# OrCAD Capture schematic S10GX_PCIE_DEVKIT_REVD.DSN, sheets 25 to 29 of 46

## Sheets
25 FMC Port A: size C
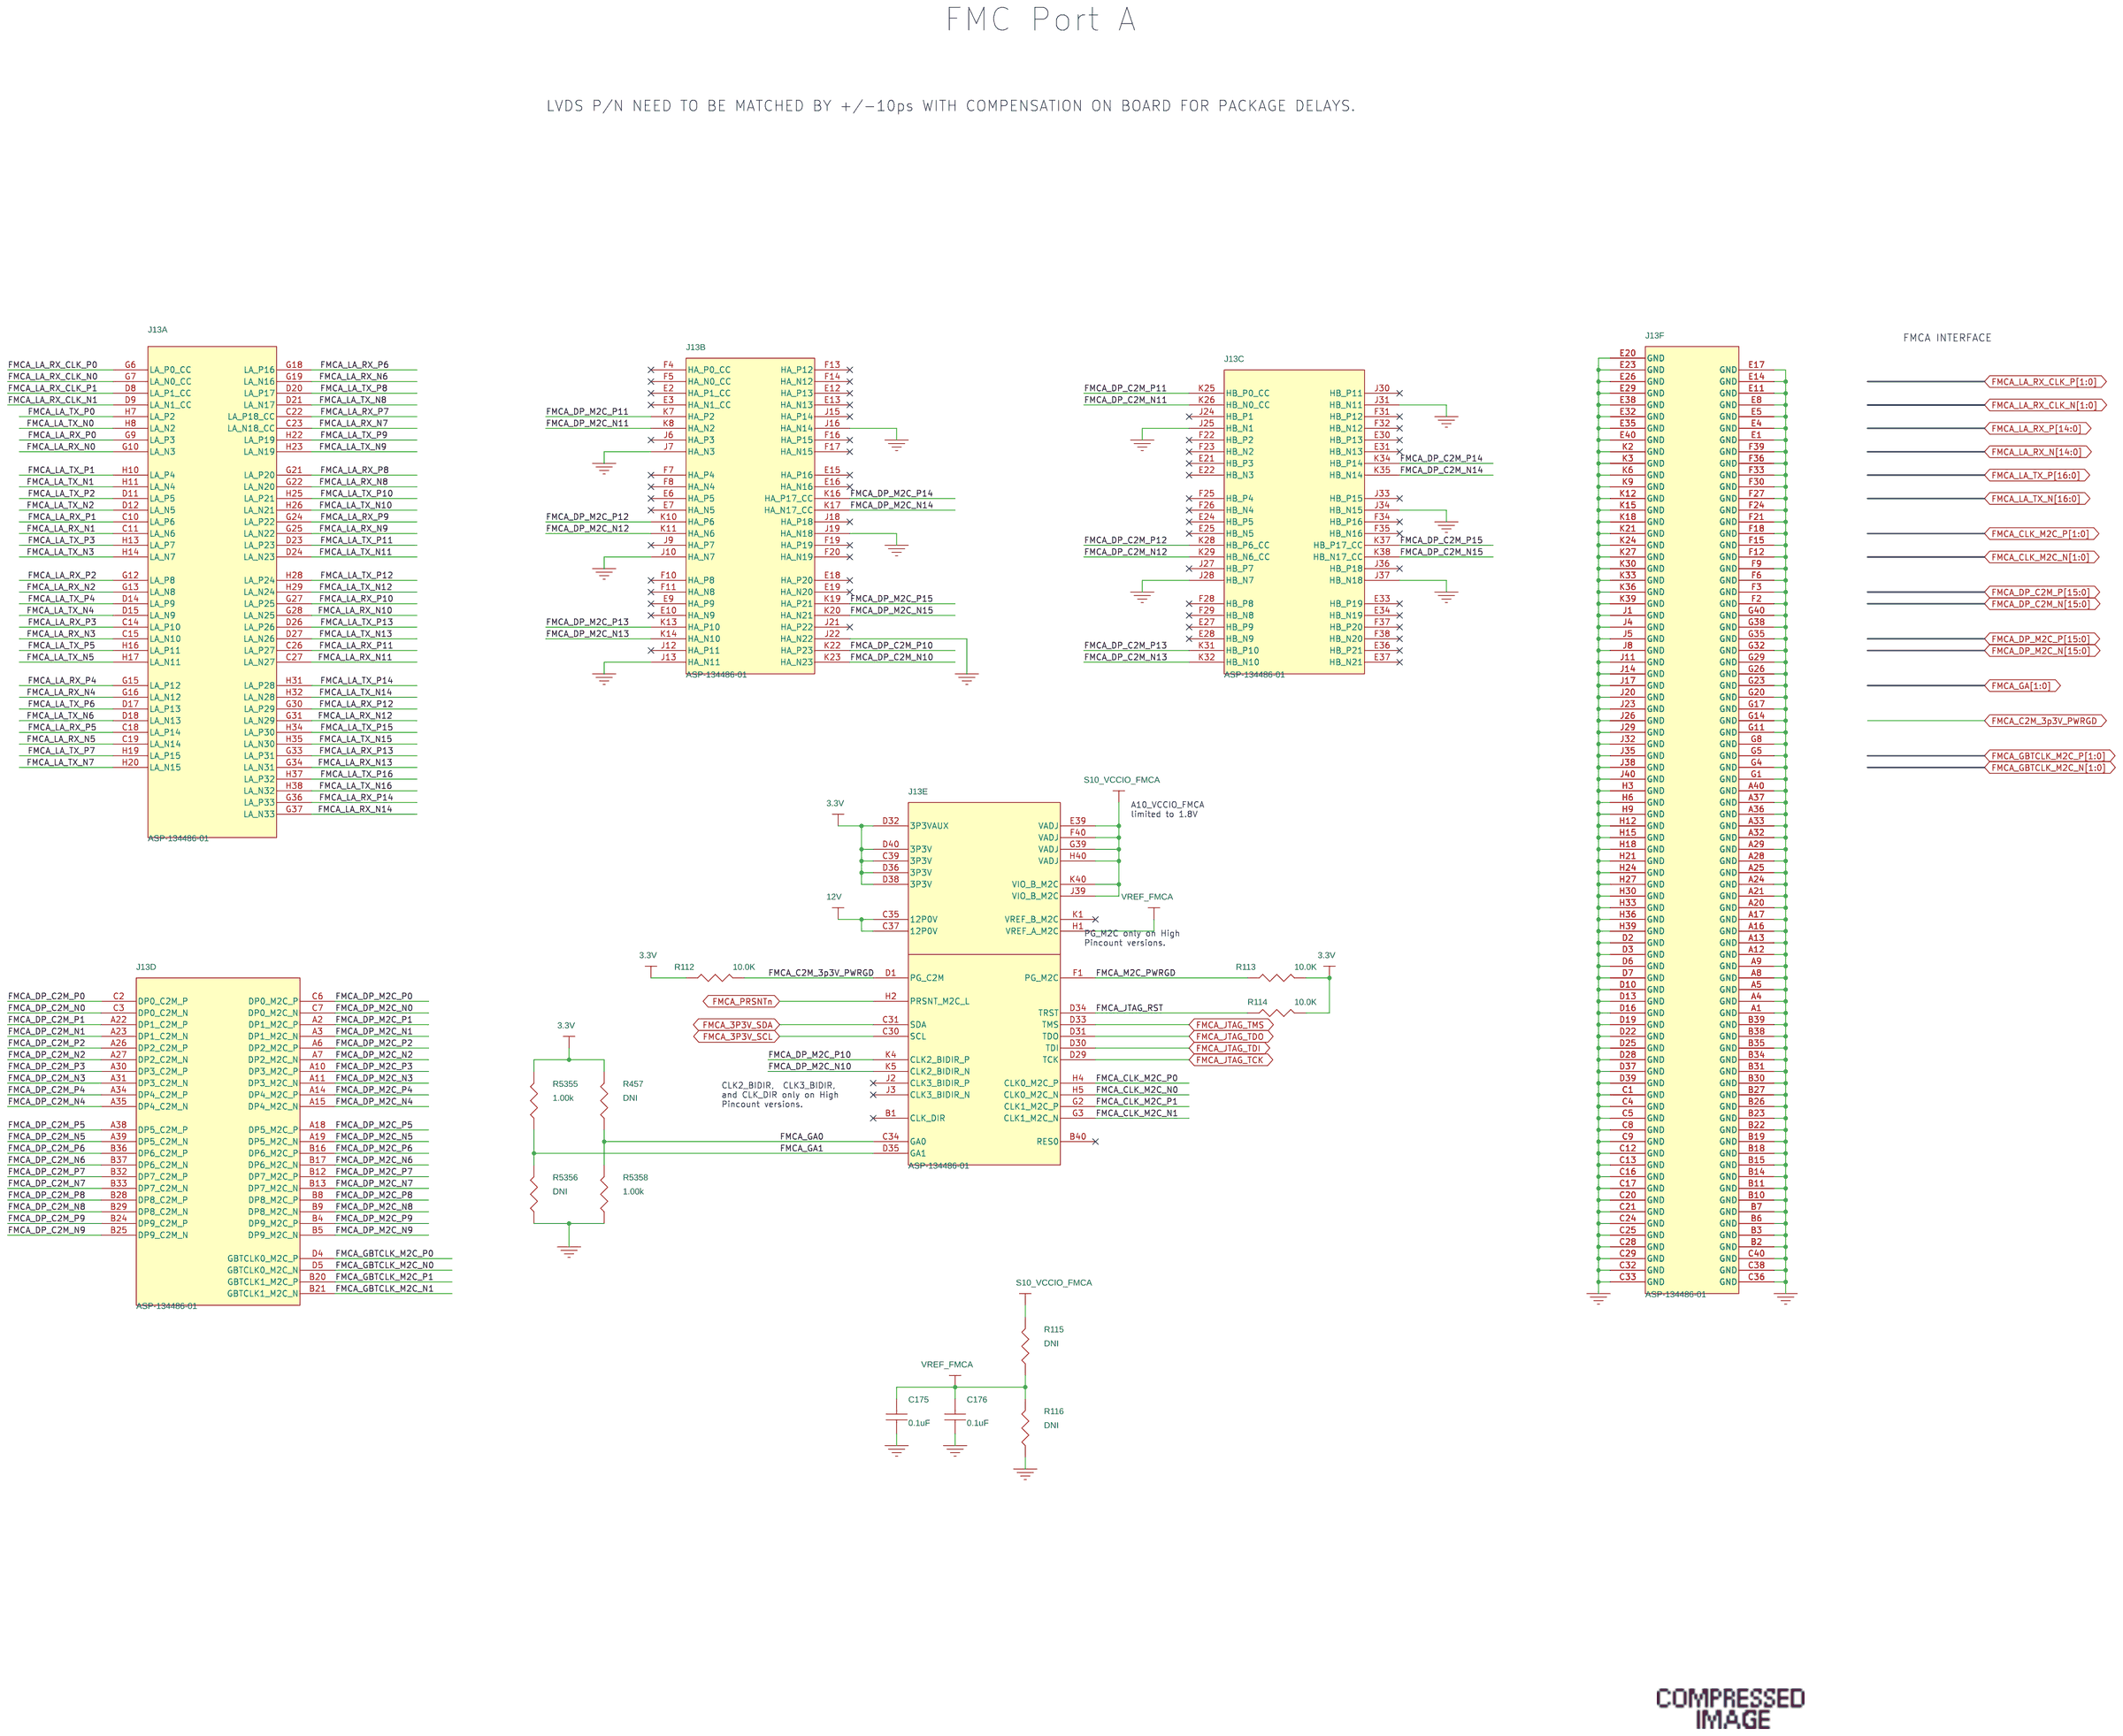
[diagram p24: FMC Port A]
26 Blank
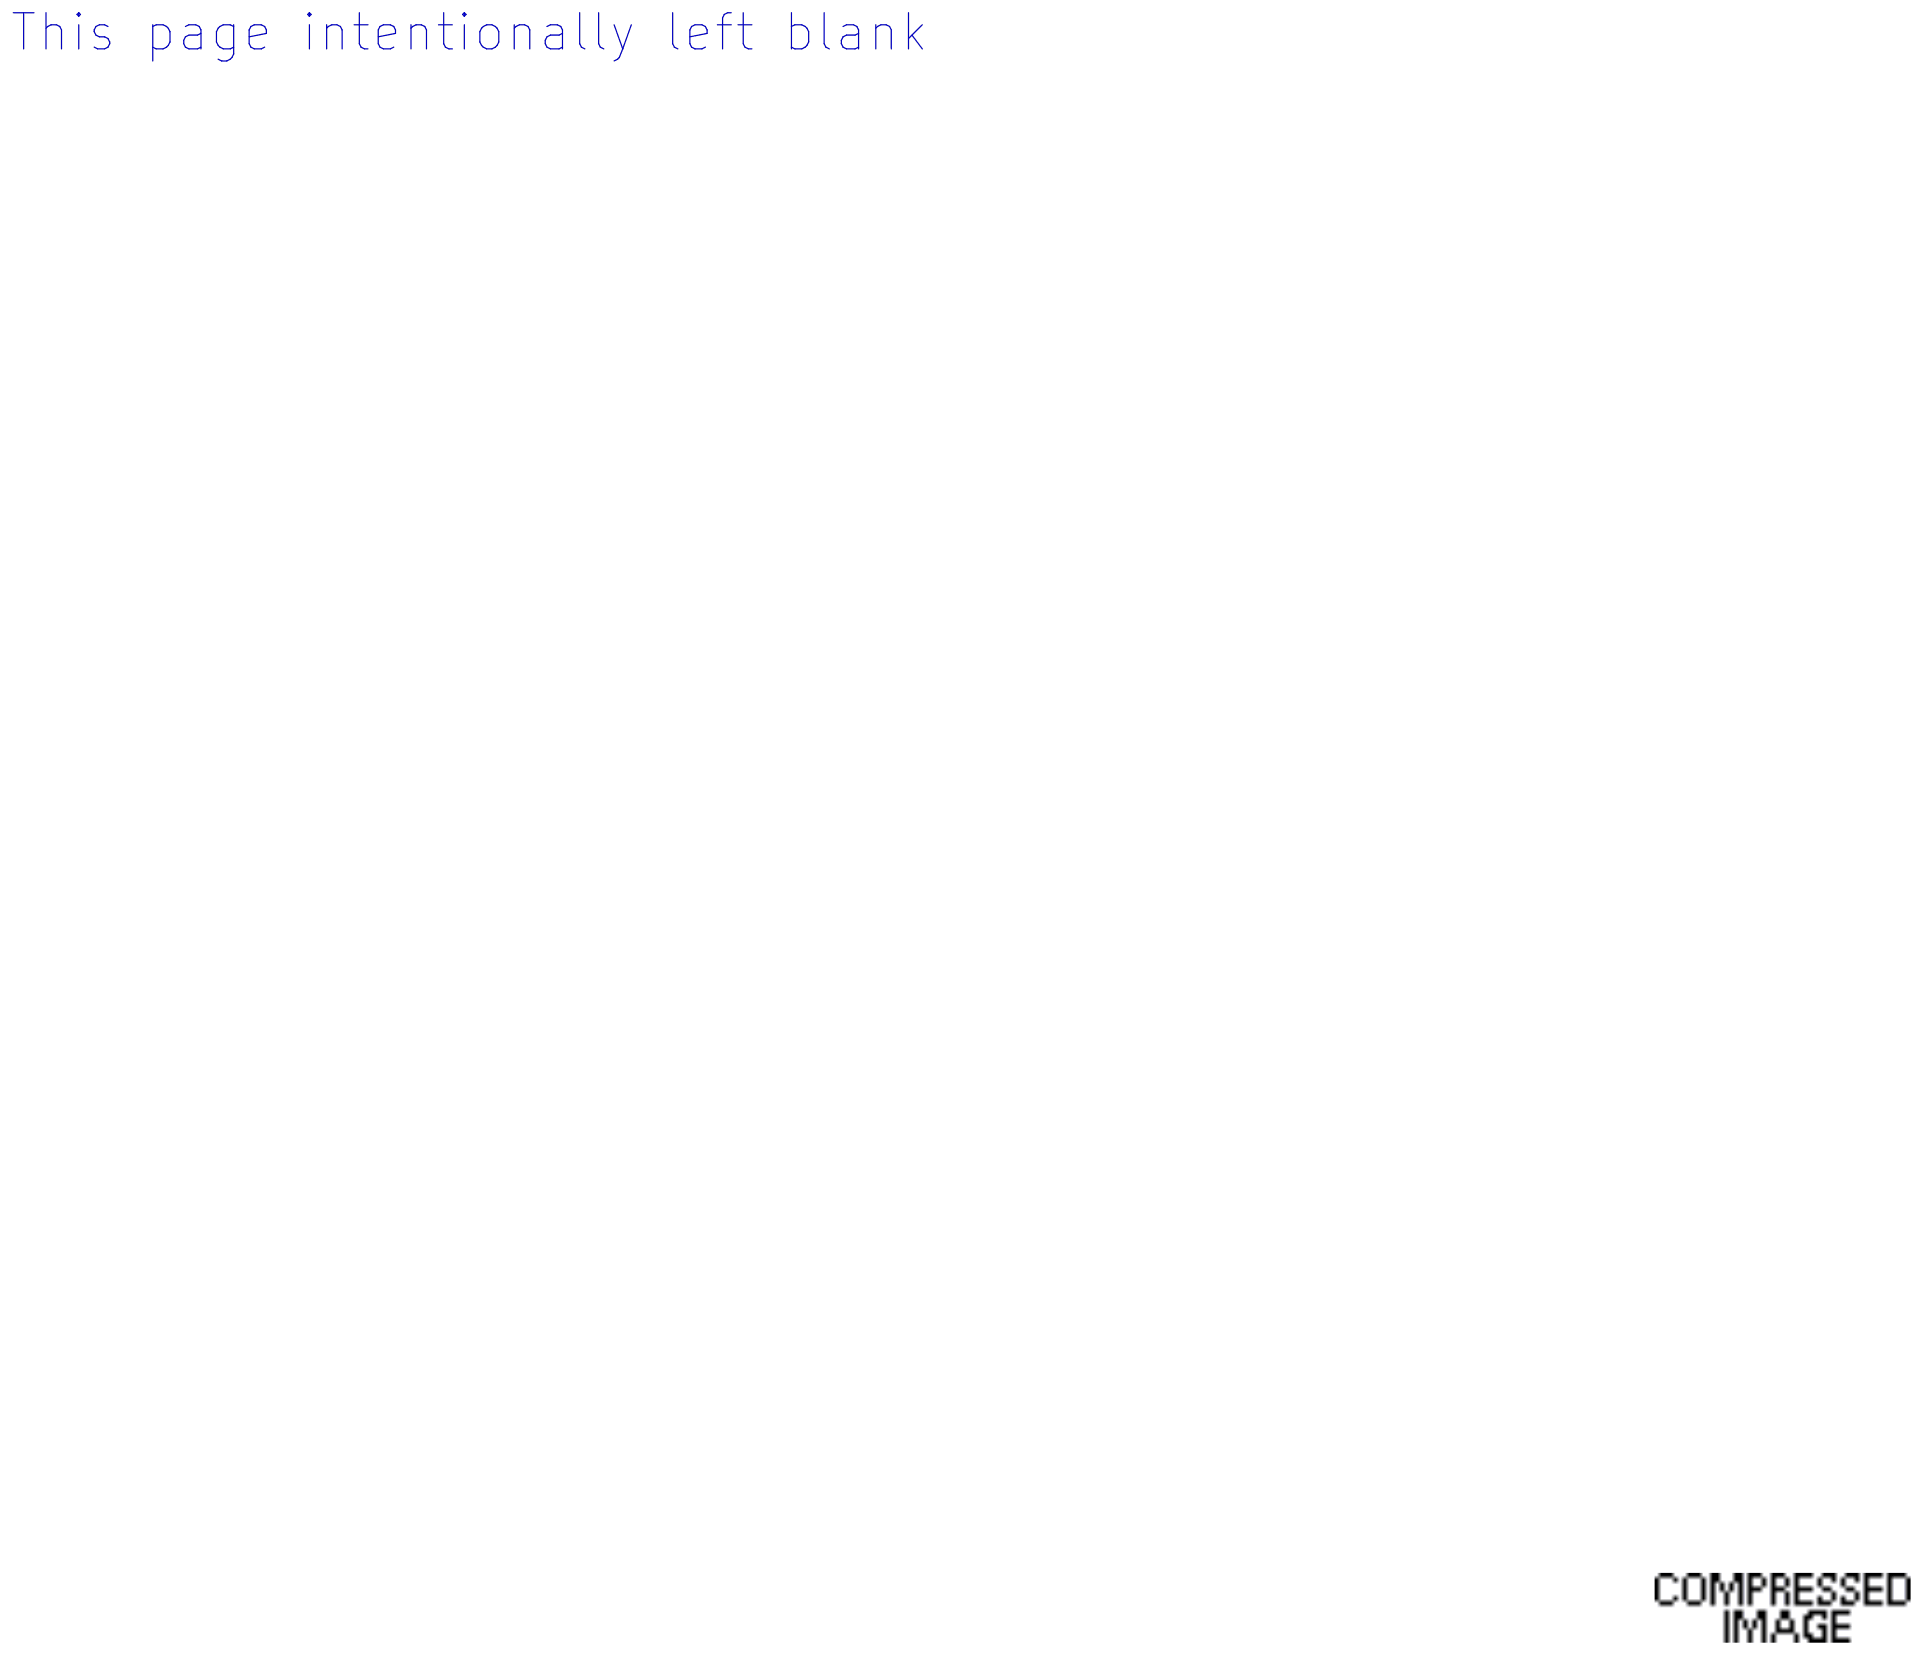
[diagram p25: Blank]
27 QSFP: size C
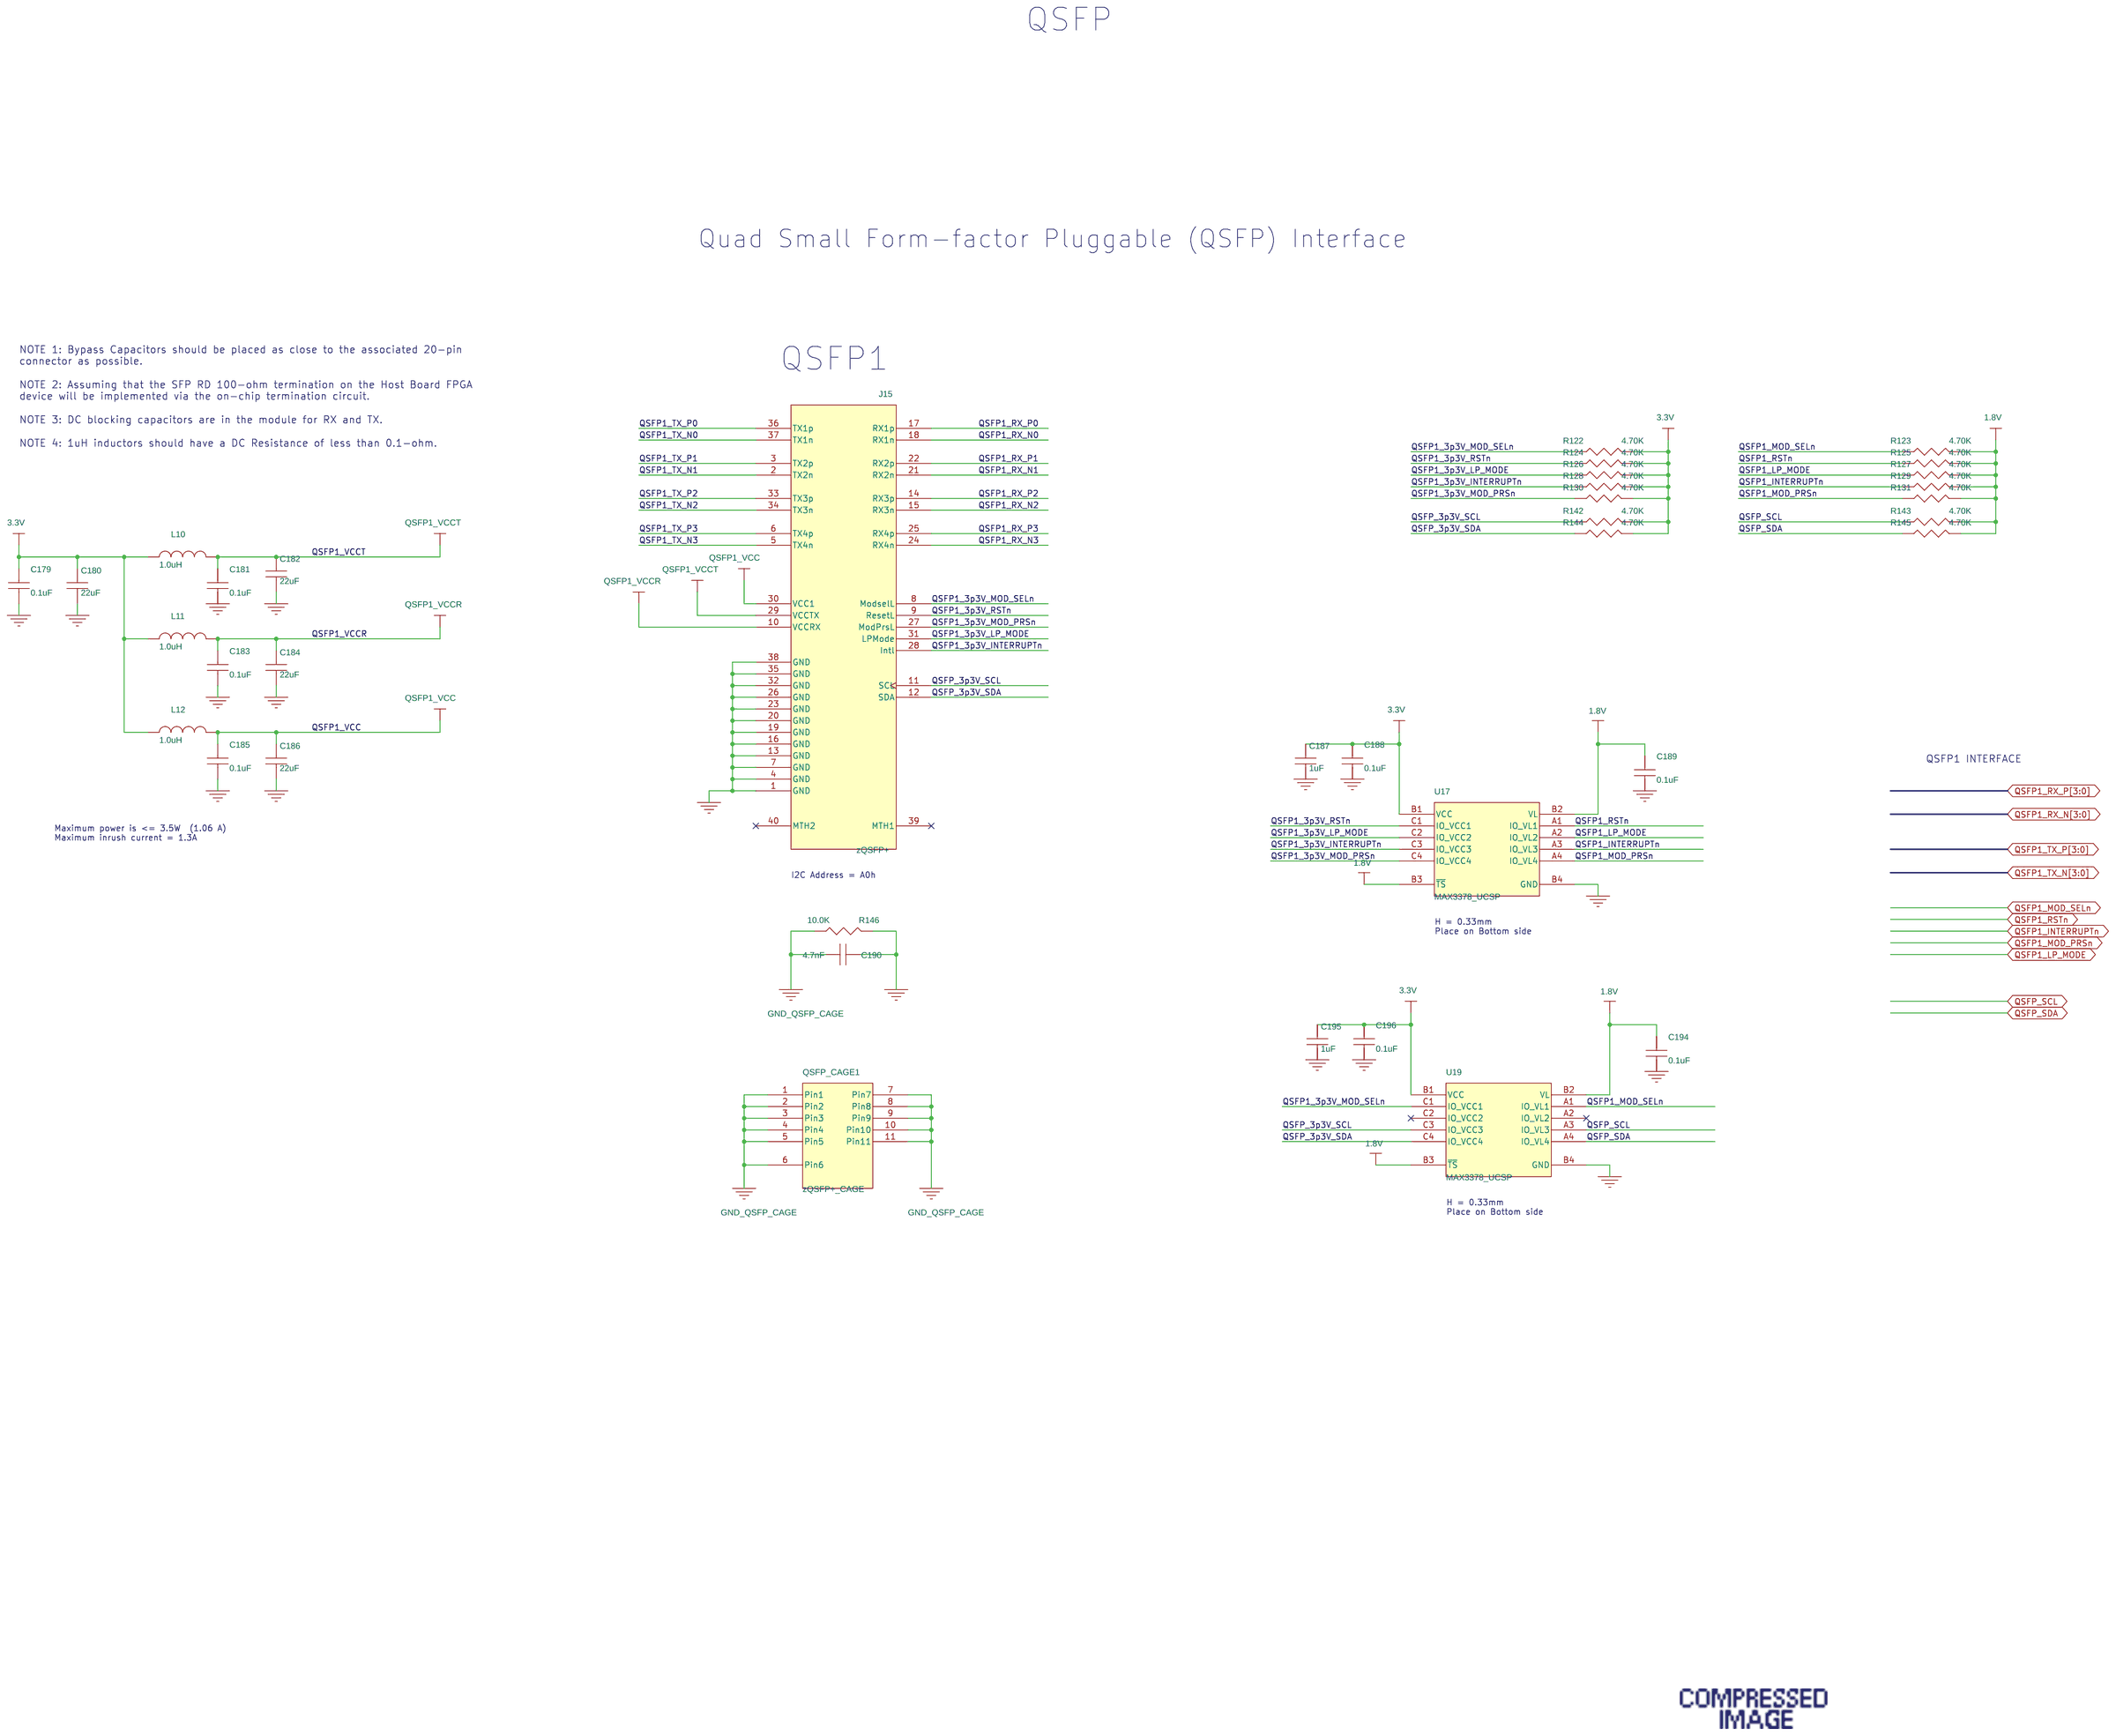
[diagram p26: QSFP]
28 12G SDI: size C
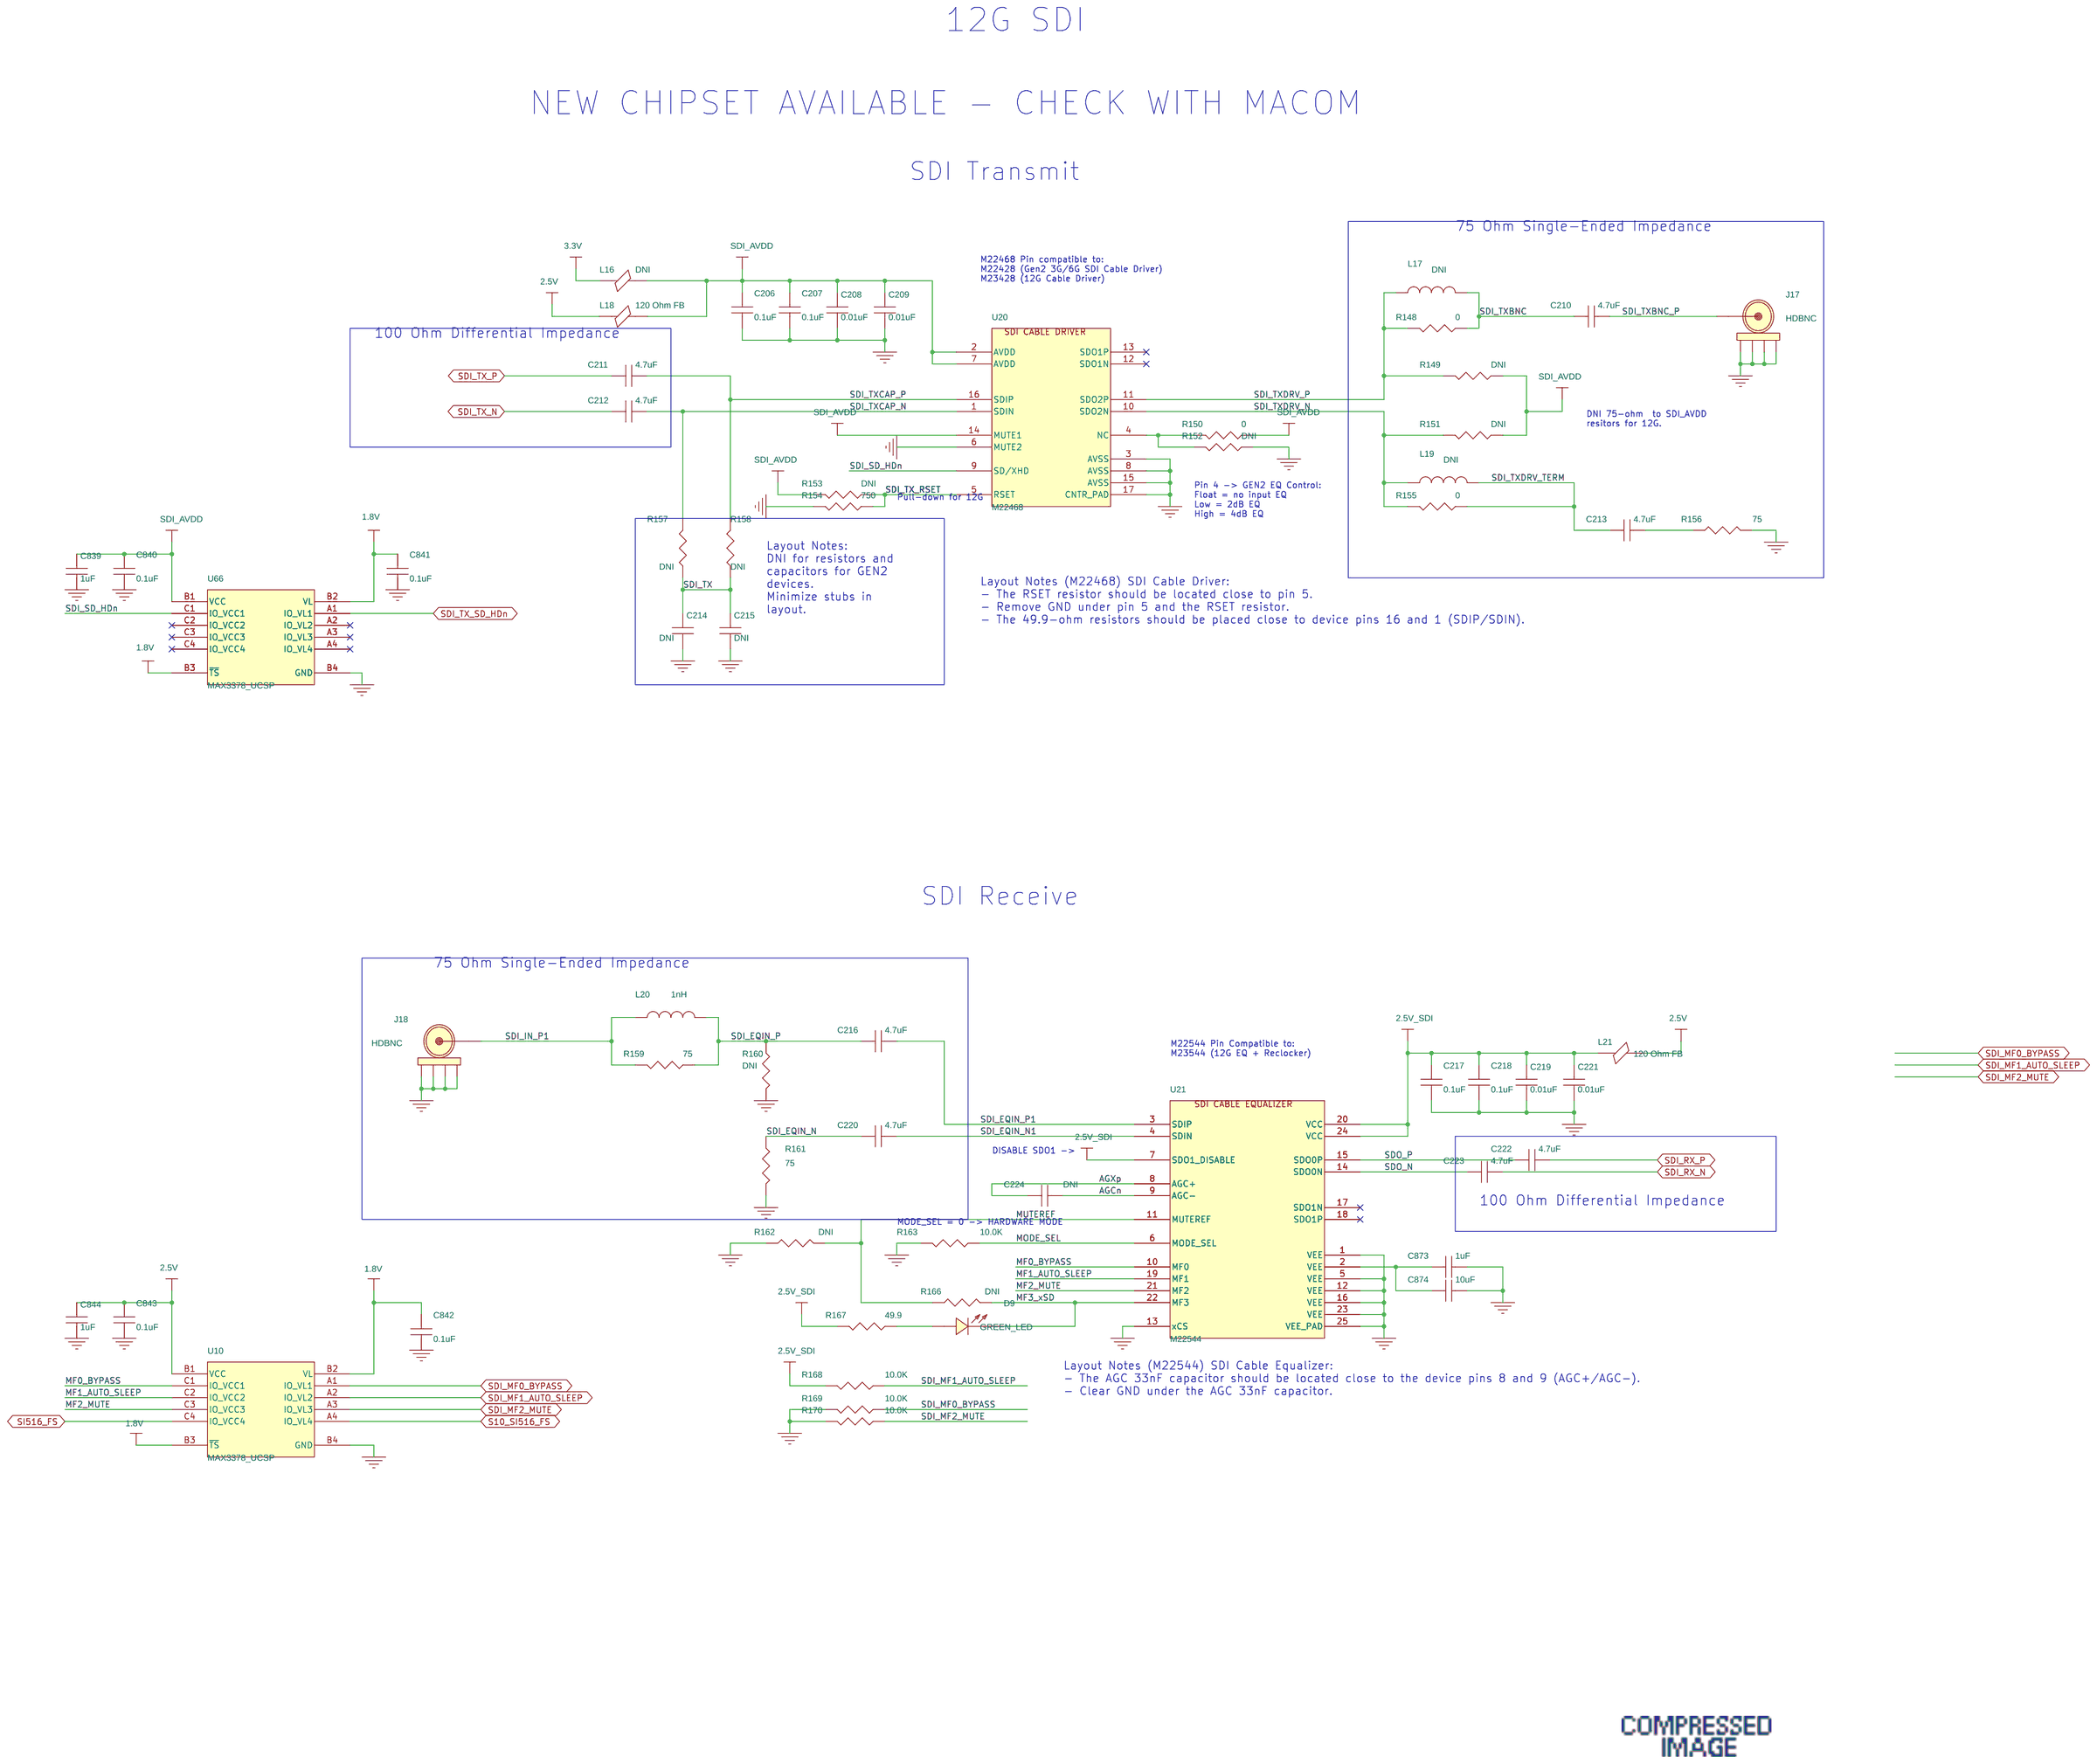
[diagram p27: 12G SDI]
29 User PB, SW, I/Os: size C
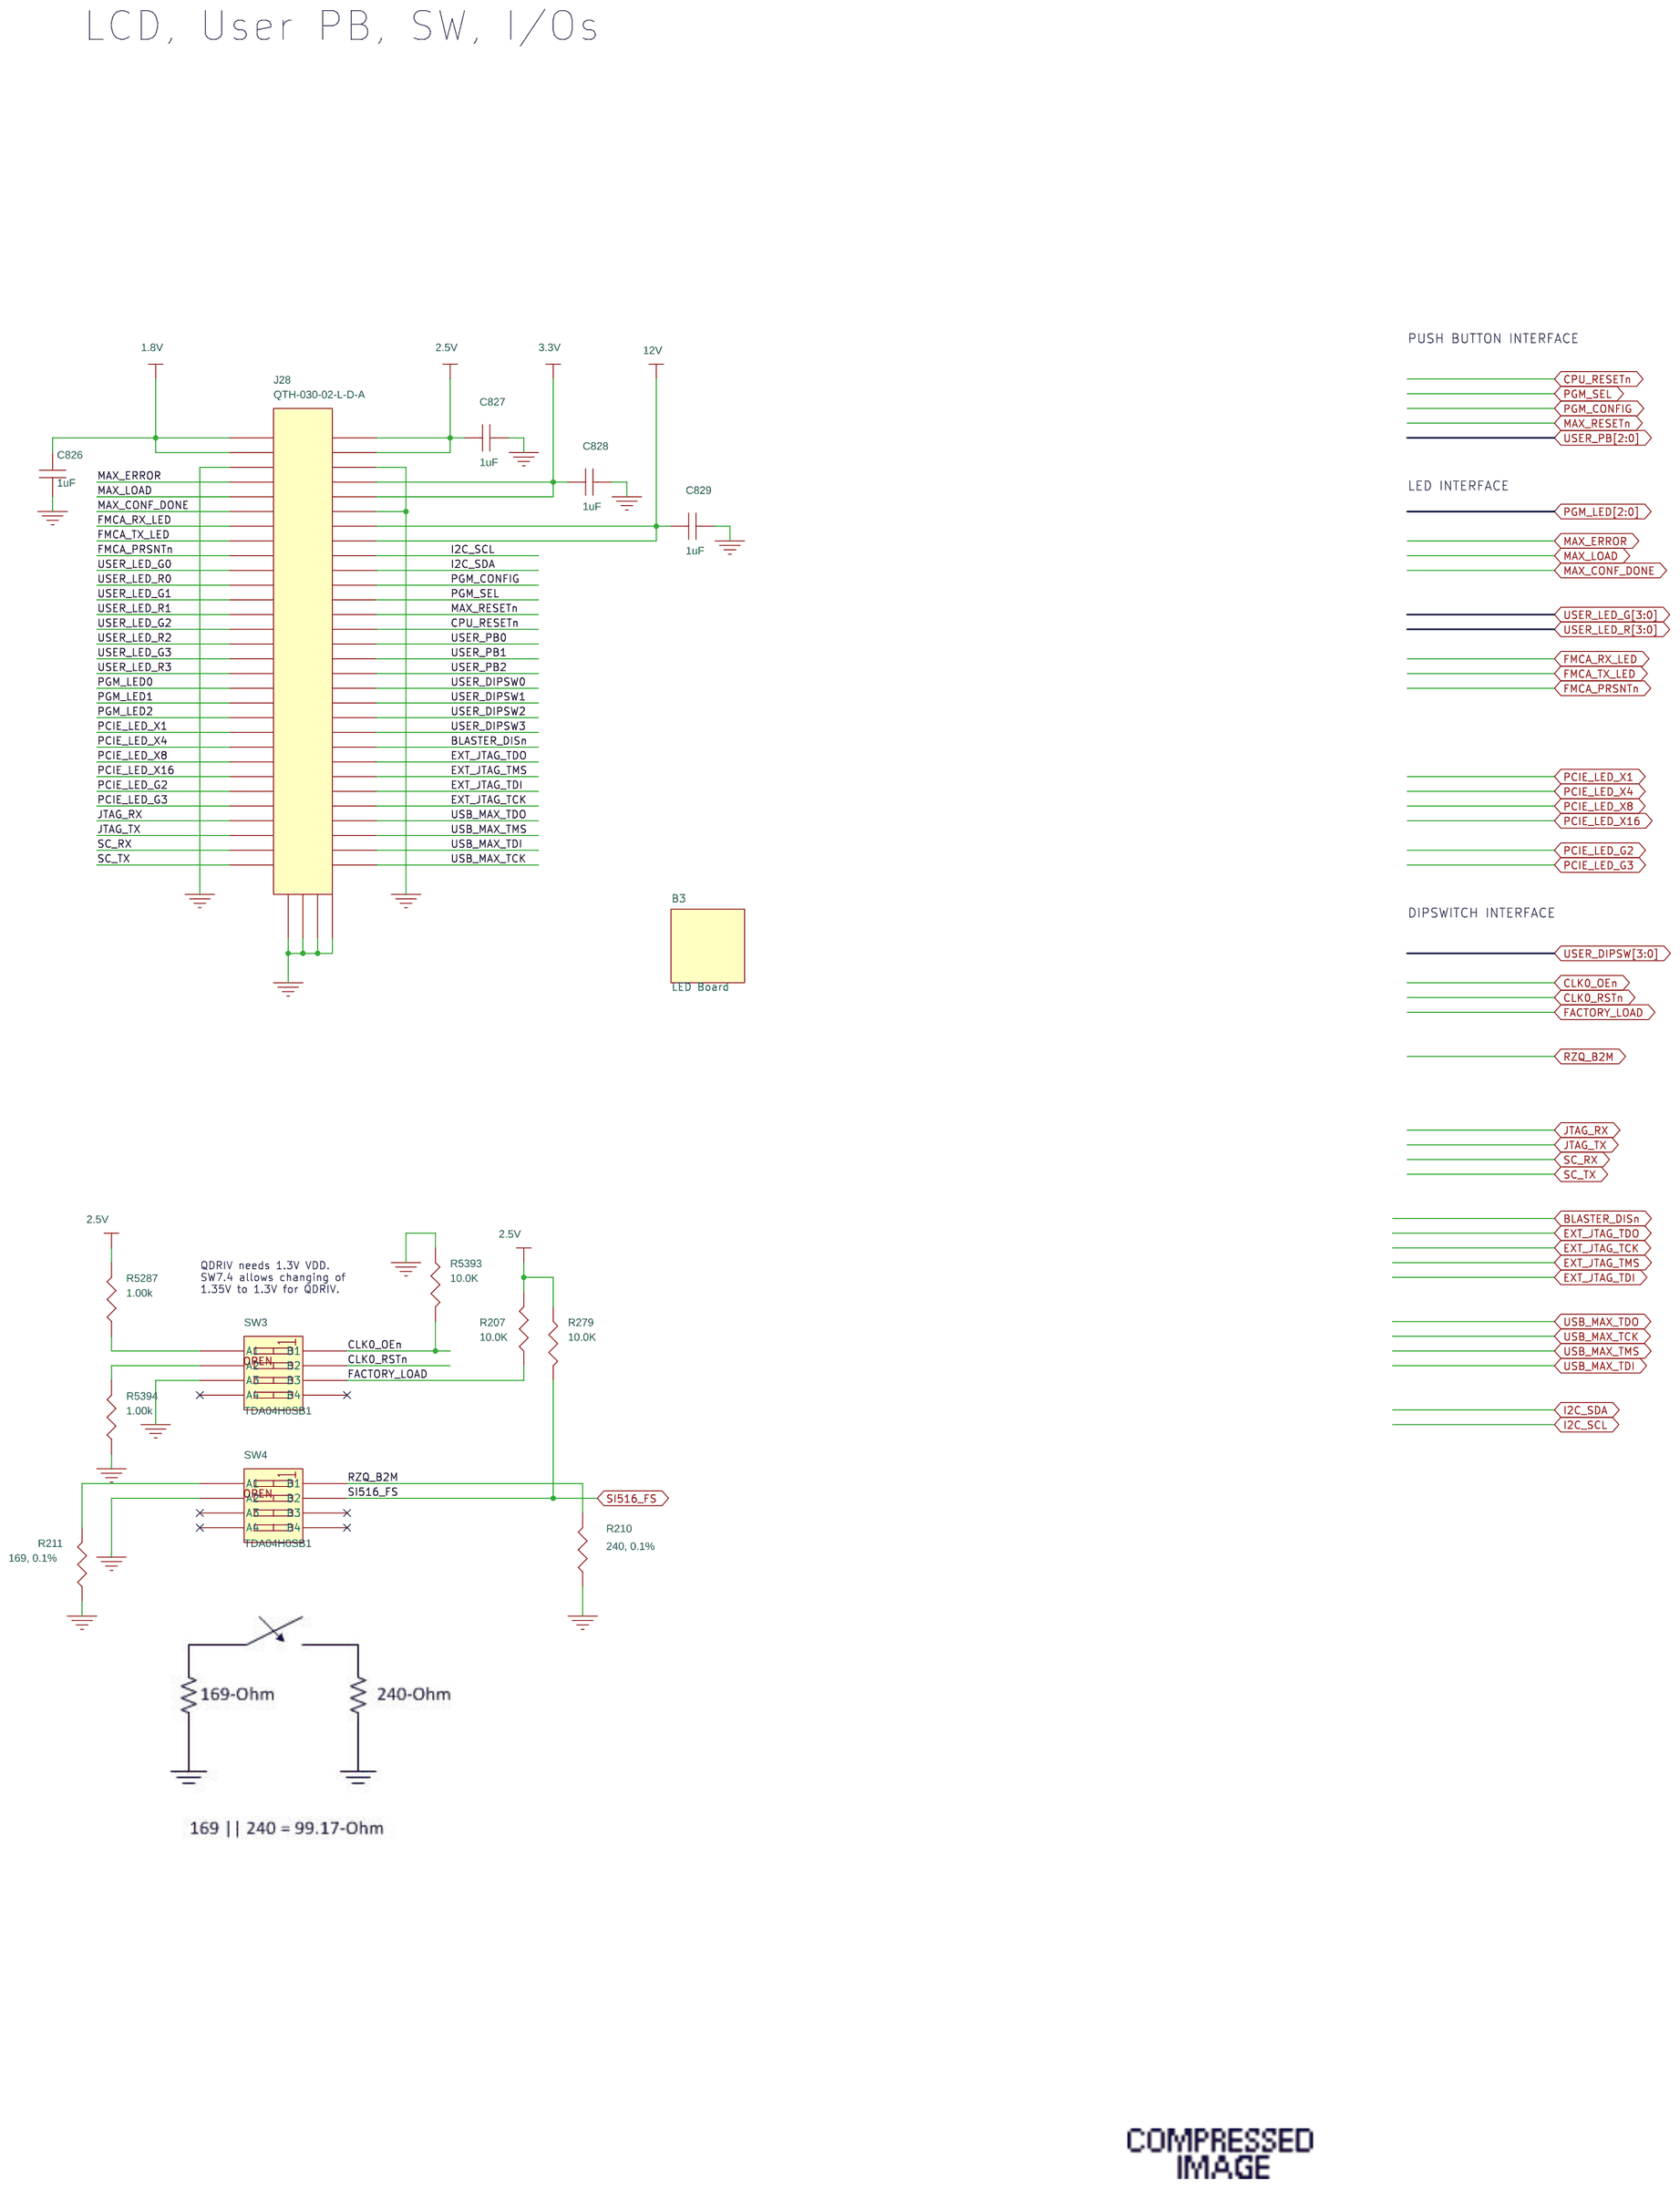
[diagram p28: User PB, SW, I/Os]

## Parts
sheet 12G SDI
C206  0.1uF  [0402]
C207  0.1uF  [0402]
C208  0.01uF  [0402]
C209  0.01uF  [0402]
C210  4.7uF  [0402]
C211  4.7uF  [0402]
C212  4.7uF  [0402]
C213  4.7uF  [0402]
C214  DNI  [0402]
C215  DNI  [0402]
C216  4.7uF  [0402]
C217  0.1uF  [0402]
C218  0.1uF  [0402]
C219  0.01uF  [0402]
C220  4.7uF  [0402]
C221  0.01uF  [0402]
C222  4.7uF  [0402]
C223  4.7uF  [0402]
C224  DNI  [0402]
C839  1uF  [0402]
C840  0.1uF  [0402]
C841  0.1uF  [0402]
C842  0.1uF  [0402]
C843  0.1uF  [0402]
C844  1uF  [0402]
C873  1uF  [0402]
C874  10uF  [0402]
D9  GREEN_LED  [LED_0603]
J17  HDBNC  [HDBNC_RA_JACK_RECEP]
J18  HDBNC  [HDBNC_RA_JACK_RECEP]
L16  DNI  [0603]
L17  DNI  [0402]
L18  120 Ohm FB  [0603]
L19  DNI  [0402]
L20  1nH  [0402]
L21  120 Ohm FB  [0603]
R148  0  [0402]
R149  DNI  [0402]
R150  0  [0402]
R151  DNI  [0402]
R152  DNI  [0402]
R153  DNI  [0603]
R154  750  [0603]
R155  0  [0402]
R156  75  [0402]
R157  DNI  [0402]
R158  DNI  [0402]
R159  75  [0402]
R160  DNI  [0402]
R161  75  [0402]
R162  DNI  [0402]
R163  10.0K  [0402]
R166  DNI  [0402]
R167  49.9  [0402]
R168  10.0K  [0402]
R169  10.0K  [0402]
R170  10.0K  [0402]
U10  MAX3378_UCSP  [UCSP-12]
U20  M22468  [MLF-16]
U21  M22544  [QFN24]
U66  MAX3378_UCSP  [UCSP-12]
sheet FMC Port A
C175  0.1uF  [0402]
C176  0.1uF  [0402]
J13  ASP-134486-01  [10x40_ASP_Vita57]  (sections A,B,C,D,E,F)
R112  10.0K  [0402]
R113  10.0K  [0402]
R114  10.0K  [0402]
R115  DNI  [0402]
R116  DNI  [0402]
R457  DNI  [0402]
R5355  1.00k  [0402]
R5356  DNI  [0402]
R5358  1.00k  [0402]
sheet QSFP
C179  0.1uF  [0402]
C180  22uF  [1210]
C181  0.1uF  [0402]
C182  22uF  [1210]
C183  0.1uF  [0402]
C184  22uF  [1210]
C185  0.1uF  [0402]
C186  22uF  [1210]
C187  1uF  [0402]
C188  0.1uF  [0402]
C189  0.1uF  [0402]
C190  4.7nF  [0402]
C194  0.1uF  [0402]
C195  1uF  [0402]
C196  0.1uF  [0402]
J15  zQSFP+  [170432-0001]
L10  1.0uH  [IND_WURTH_74479775210]
L11  1.0uH  [IND_WURTH_74479775210]
L12  1.0uH  [IND_WURTH_74479775210]
QSFP_CAGE1  zQSFP+_CAGE  [QSFP_CAGE1]
R122  4.70K  [0402]
R123  4.70K  [0402]
R124  4.70K  [0402]
R125  4.70K  [0402]
R126  4.70K  [0402]
R127  4.70K  [0402]
R128  4.70K  [0402]
R129  4.70K  [0402]
R130  4.70K  [0402]
R131  4.70K  [0402]
R142  4.70K  [0402]
R143  4.70K  [0402]
R144  4.70K  [0402]
R145  4.70K  [0402]
R146  10.0K  [0402]
U17  MAX3378_UCSP  [UCSP-12]
U19  MAX3378_UCSP  [UCSP-12]
sheet User PB, SW, I/Os
B3  LED Board
C826  1uF  [0402]
C827  1uF  [0402]
C828  1uF  [0402]
C829  1uF  [0402]
J28  QTH-030-02-L-D-A  [QTH-030]
R207  10.0K  [0402]
R210  240, 0.1%  [0603]
R211  169, 0.1%  [0603]
R279  10.0K  [0402]
R5287  1.00k  [0402]
R5393  10.0K  [0402]
R5394  1.00k  [0402]
SW3  TDA04H0SB1  [DIPSWITCH_SMT_QUAD]
SW4  TDA04H0SB1  [DIPSWITCH_SMT_QUAD]

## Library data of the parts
C188 C189 C194 C196 C206 C207 C217 C218 C840-C843 = CAP: CAP - CERAMIC,  0.1UF 0402 25VDC Y5V; Dielectric: Y5V; Item Num: P03-15057R; LIFECYCLE_PHASE: Active; Lead Free Status: Lead Free; MFR_LIFECYCLE: Active; Manufacturer: Murata; Manufacturer Part Num: GRM155F51E104ZA01D; Num Pins: 2; PART_SUBCLASS: CAPACITORS; Part Class: CAPACITORS; RATED_VOLTAGE: 25V; RoHS Compliant: RoHS Compliant; Tolerance: +80%/-20%
C208 C209 C214 C215 C219 C221 = CAP: CAP - CER, 10NF, 50V, +/-10%, X7R, 0402 SMD; Dielectric: X5R; Item Num: P03-16318R; Lead Free Status: Yes; Manufacturer: Murata; Manufacturer Part Num: GRM155R71H103KA88D; Manufacturer's Part No.: GRM155R71H103KA88D; Num Pins: 2; Part Class: CAPACITORS; Price: 0.07; RoHS Compliant: Yes; Tolerance: 10%
C210-C213 C216 C220 C222 C223 = CAP: CAP - CERAMIC, 4.7UF, 6.3V, 10%, X5R, 0402; AGILE_LINK: http://sj-agile9app/Agile/PLMServlet?action=OpenEmailObject&classid=10000&objid=257560276; Item Num: P03-17432R; LIFECYCLE_PHASE: Active; Lead Free Status: Not Lead Free; MFR_LIFECYCLE: Active; Manufacturer: Murata; Manufacturer Part Num: GRM155R60J475ME87D; Num Pins: 2; PART_SUBCLASS: CAPACITORS; RATED_VOLTAGE: 6.3V; RoHS Compliant: RoHS Compliant; TOLERANCE: +/-10%
C224 = CAP: CAP, CERAMIC, 33000PF, 0402, 10%, 10VDC, X5R; Item Num: P03-15011R; Lead Free Status: Yes; Manufacturer: Murata; Manufacturer Part Num: GRM155R61A333KA01D; Num Pins: 2; Part Class: CAPACITORS; RoHS Compliant: Yes
C187 C195 C826-C829 C839 C844 C873 = CAP: CAP - CER, 1uF, 10V, +/-10%, X5R, 0402; Item Num: P03-15479R; Lead Free Status: Yes; Manufacturer: Murata; Manufacturer Part Num: GRM155R61A105KE15D; Num Pins: 2; Part Class: CAPACITORS; RoHS Compliant: Yes
C874 = CAP: CAP - 10UF 6.3V CERAMIC CAPACITOR X5R 0402; Item Num: P03-17886R; Lead Free Status: Yes; Manufacturer: Murata; Manufacturer Part Num: GRM155R60J106ME44D; Num Pins: 2; Part Class: CAPACITORS; RoHS Compliant: Yes
D9 = LED_WURTH: LED - BRIGHT GREEN, VF=2V, IF=0.03A, 0603; Item Num: P09-21344R; LIFECYCLE_PHASE: Active; Lead Free Status: Lead Free; Manufacturer: Wurth Electroniks; Manufacturer Part Num: 150060VS75000; Num Pins: 2; PART_SUBCLASS: LEDS; Part Class: LEDS; RoHS Compliant: RoHS Compliant
J17 J18 = CONN,_mini_SMB,_THM,_RA: 75ohm High Density BNC Jacks; Item Num: P23-38673R; Manufacturer: Samtec; Manufacturer Part Num: HDBNC-J-P-GN-RA-BH2
L16 L18 L21 = BEAD_FERRITE_SM: IND - EMIFIL FERRITE BEAD, 120 OHM, 25%, 0603; Item Num: P04-16045R; Lead Free Status: No; Manufacturer: Murata; Manufacturer Part Num: BLM18PG121SN1; Num Pins: 2; Part Class: Inductors; Price: 0; RoHS Compliant: Yes
L17 L19 = INDUCTOR: IND - 3.9NH, 5%, 0402; AGILE_LINK: http://sj-agile9app/Agile/PLMServlet?action=OpenEmailObject&classid=10000&objid=259659196; Item Num: P04-16446R; LIFECYCLE_PHASE: Preliminary; Lead Free Status: Lead Free; MFR_LIFECYCLE: Active; Manufacturer: Coilcraft; Manufacturer Part Num: 0402CS-3N9XJLx; Num Pins: 2; PART_SUBCLASS: INDUCTORS; RoHS Compliant: RoHS Compliant
L20 = INDUCTOR: INDUCTOR FILM RF 1NH AT 500MHZ 400MA 0402 (Murata); AGILE_LINK: http://sj-agile9app/Agile/PLMServlet?action=OpenEmailObject&classid=10000&objid=215176093; Item Num: P04-17107R; LIFECYCLE_PHASE: Active; MFR_LIFECYCLE: Active; Manufacturer: Murata; Manufacturer Part Num: LQP15MN1N0B02D; Num Pins: 2; PACKAGING: Tape Reel; PART_SUBCLASS: INDUCTORS; RoHS Compliant: RoHS Compliant
R148 R150 R155 = RESISTOR: RES ZERO OHM 1/16W 5% 0402 SMD; Altera Part No.: P02-14020R; Item Num: P02-14020R; Lead Free Status: No; Manufacturer: Panasonic; Manufacturer Part Num: ERJ-2GE0R00X; Num Pins: 2; Part Class: RESISTORS; RoHS Compliant: Yes; Tolerance: 5%
R149 R151 R156 R159-R161 = RESISTOR: RES, 75 OHM, 5%, 1/16W, 0402; Item Num: P02-14103R; Lead Free Status: No; Manufacturer: Panasonic; Manufacturer Part Num: ERJ-2GEJ750X; Num Pins: 2; Part Class: Resistors; Price: 0
R152 R162 R166 = RESISTOR: RES ZERO OHM 1/16W 5% 0402 SMD; Altera Part No.: P02-14020R; Item Num: P02-14020R; Lead Free Status: No; Manufacturer: Panasonic; Manufacturer Part Num: ERJ-2GE0R00X; Num Pins: 2; Part Class: RESISTORS; Price: 0; RoHS Compliant: Yes; Tolerance: 5%
R153 R154 = RESISTOR: RES, 750 OHMS, 5%, 1/10W, 0603; Item Num: P02-14118R; Lead Free Status: No; Manufacturer: Panasonic; Manufacturer Part Num: ERJ-3GEYJ751V; Num Pins: 2; Part Class: Resistors; Price: 0
R157 R158 R167 = RESISTOR: RES, 49.9 OHMS, 1%, 1/16W, 0402; Item Num: P02-14101R; Lead Free Status: Yes; Manufacturer: NIC Components Corp.; Manufacturer Part Num: NRC04F49R9TRF; Num Pins: 2; Part Class: Resistors; Price: 0
R112-R114 R146 R163 R168-R170 R207 R279 R5393 = RESISTOR: RES,10.0K OHMS,1.0%,1/16W, 0402; AGILE_LINK: http://sj-agile9app/Agile/PLMServlet?action=OpenEmailObject&classid=10000&objid=146548997; Item Num: P02-11364R; LIFECYCLE_PHASE: Active; Lead Free Status: No; MFR_LIFECYCLE: Active; Manufacturer: Panasonic; Manufacturer Part Num: ERJ-2RKF1002X; Num Pins: 2; PART_SUBCLASS: RESISTORS; POWER: 1/16W; RoHS Compliant: Yes; TOLERANCE: +/-1%
U10 U17 U19 U66 = MAX3378_12UCSP: IC - QUAD LOW-VOLTAGE LEVEL TRANSLATOR, +/- 15KV, ESD-PROTECTED, 1UA, 8-16MBPS, 12-UCSP (1.5X2)MM; Item Num: P01-17875R; Lead Free Status: Yes; Manufacturer: Maxim Integrated Products, Inc.; Manufacturer Part Num: MAX3378EEBC+; Num Pins: 12; Part Class: ICs; RoHS Compliant: Yes
U20 = M22468: IC - 6G/3G/HD/SD-SDI CABLE DRIVER 143M-5.94M BIT/SEC, DUAL OUTPUT, 16-PIN MLF (3MM X 3MM); Item Num: P01-17929R; Lead Free Status: Yes; Manufacturer: MINDSPEED; Manufacturer Part Num: M23428G-33; Num Pins: 17; Part Class: ICS
U21 = M22544: IC - 6G/3G/HD/SD-SDI ADAPTIVE CABLE EQUALIZER 125M-5.94M BIT/SEC, DUAL OUTPUT, 24-QFN (4MM x 4MM); Item Num: P01-17930R; LIFECYCLE_PHASE: Active; Lead Free Status: Lead Free; MFR_LIFECYCLE: Active; Manufacturer: MINDSPEED; Manufacturer Part Num: M23544G-14; Num Pins: 25; PART_SUBCLASS: ICS; RoHS Compliant: RoHS Compliant
C175 C176 = CAP: CAP - CERAMIC,  0.1UF 0402 25VDC Y5V; Dielectric: Y5V; Item Num: P03-15057R; LIFECYCLE_PHASE: Active; Lead Free Status: Lead Free; MFR_LIFECYCLE: Active; Manufacturer: Murata; Manufacturer Part Num: GRM155F51E104ZA01D; Num Pins: 2; PART_SUBCLASS: CAPACITORS; Part Class: CAPACITORS; RATED_VOLTAGE: 25V; RoHS Compliant: RoHS Compliant; TOLERANCE: +80%/-20%
J13 = 10x40_Vita57_4: CONN - 0.050 Pitch Socket Array Assembly, 10x40 pin array; COMPGROUP: FMCA; Item Num: P23-38435R; Manufacturer: Samtec
R115 R116 = RESISTOR: RES,100 OHMS,1.0%,1/16W,0402; Item Num: P02-11381R; Lead Free Status: No; Manufacturer: Panasonic; Manufacturer Part Num: ERJ-2RKF1000X; Num Pins: 2; Part Class: Resistors; Price: 0; RoHS Compliant: Yes; Tolerance: 1%
R457 R5287 R5355 R5356 R5358 R5394 = RESISTOR: RES,1.00K OHMS,1.0%,1/16W,0402; Item Num: P02-11372R; Lead Free Status: No; Manufacturer: Panasonic; Manufacturer Part Num: ERJ-2RKF1001X; Num Pins: 2; Part Class: Resistors
C179 C181 C183 C185 = CAP: CAP - CERAMIC,  0.1UF 0402 25VDC Y5V; Dielectric: X5R; Item Num: P03-15057R; LIFECYCLE_PHASE: Active; Lead Free Status: Lead Free; Manufacturer: Murata; Manufacturer Part Num: GRM155F51E104ZA01D; Num Pins: 2; Part Class: CAPACITORS; Price: 0.07; RoHS Compliant: RoHS Compliant; Tolerance: +80%/-20%
C180 C182 C184 C186 = CAP: CAP - CERAMIC 22UF 10V X5R 10% 1210; AGILE_LINK: http://sj-agile9app/Agile/PLMServlet?action=OpenEmailObject&classid=10000&objid=216565517; Item Num: P03-15081R; LIFECYCLE_PHASE: Active; Lead Free Status: Lead Free; MFR_LIFECYCLE: Active; Manufacturer: Murata; Manufacturer Part Num: GRM32ER61A226KE20L; Num Pins: 2; PART_SUBCLASS: CAPACITORS; RATED_VOLTAGE: 10V; RoHS Compliant: RoHS Compliant; TOLERANCE: +/-10%
C190 = CAP: CAP - CER 4700PF 50V 10% X7R 0402; AGILE_LINK: http://sj-agile9app/Agile/PLMServlet?action=OpenEmailObject&classid=10000&objid=215384813; Item Num: P03-15074R; LIFECYCLE_PHASE: Active; Lead Free Status: Lead Free; MFR_LIFECYCLE: Active; Manufacturer: Murata; Manufacturer Part Num: GRM155R71H472KA01D; Num Pins: 2; PACKAGING: Tape & Reel (TR); PART_SUBCLASS: CAPACITORS; RATED_VOLTAGE: 50V; RoHS Compliant: RoHS Compliant; Supplier Part Num: GRM155R71H472KA01D; Tolerance: +/-10%
J15 = molex_zQSFP+_0
L10-L12 = INDUCTOR: IND - 1.0UH, DCR=0.1-OHM, IR=1.1A, ISAT=0.7A, 0805; Item Num: P04-17099R; Manufacturer: Wurth Electronics; Manufacturer Part Num: 74479775210
QSFP_CAGE1 = BLANK_PART_2: CONN - CAGE ASSY ZQSFP+; Item Num: P23-38774R; Manufacturer: Molex; Manufacturer Part Num: 100014-1242
R122-R131 R142-R145 = RESISTOR: RES,4.70K OHMS,1.0%,1/16W,0402; AGILE_LINK: http://sj-agile9app/Agile/PLMServlet?action=OpenEmailObject&classid=10000&objid=146753272; Item Num: P02-11384R; LIFECYCLE_PHASE: Active; Lead Free Status: No; MFR_LIFECYCLE: Active; Manufacturer: Vishay; Manufacturer Part Num: CRCW04024K70FKED; Num Pins: 2; PART_SUBCLASS: RESISTORS; POWER: 1/16W; RESISTANCE: 4.7K; RoHS Compliant: Yes; TOLERANCE: +/-1%
B3 = BLANK_PART: STRATIX 10 GX FPGA LED BOARD; Item Num: 6XX-44435R; Manufacturer: Altera; Manufacturer Part Num: 6XX-44435R
J28 = HEADER_30X2_0: 60 PIN HIGH SPEED GROUND PLANE HEARDER; Item Num: P23-38641R; Manufacturer: Samtec
R210 = RESISTOR: RES - 240 OHM, 1/10W, 0.1%, 0603 SMD; AGILE_LINK: http://sj-agile9app/Agile/PLMServlet?action=OpenEmailObject&classid=10000&objid=146548997; Item Num: P02-17607R; LIFECYCLE_PHASE: Active; Lead Free Status: Yes; MFR_LIFECYCLE: Active; Manufacturer: Panasonic; Manufacturer Part Num: ERA-3AEB241V; Num Pins: 2; PART_SUBCLASS: RESISTORS; POWER: 1/10W; RoHS Compliant: Yes; TOLERANCE: +/-0.1%
R211 = RESISTOR: RES - 169 OHM, 1/10W, 0.1%, 0603 SMD; AGILE_LINK: http://sj-agile9app/Agile/PLMServlet?action=OpenEmailObject&classid=10000&objid=146548997; Item Num: P02-17606R; LIFECYCLE_PHASE: Active; Lead Free Status: Yes; MFR_LIFECYCLE: Active; Manufacturer: Panasonic; Manufacturer Part Num: ERA-3AEB1690V; Num Pins: 2; PART_SUBCLASS: RESISTORS; POWER: 1/10W; RoHS Compliant: Yes; TOLERANCE: +/-0.1%
SW3 SW4 = SPST4: SWITCHES - 4 POS, 8 PIN, Ultra-mini SMT Half-pitch Slider DIP Switch; AGILE_LINK: http://sj-agile9app/Agile/PLMServlet?action=OpenEmailObject&classid=10000&objid=258073635; Item Num: P11-24098R; LIFECYCLE_PHASE: Preliminary; Lead Free Status: Not Lead Free; MFR_LIFECYCLE: Active; Manufacturer: C & K Components/ITT Industries; Num Pins: 8; PART_SUBCLASS: SWITCHES; RoHS Compliant: RoHS Compliant

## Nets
1.8V: C189.1 C194.1 C826.1 C841.1 C842.1 J28.2 J28.4 R123.2 R125.2 R127.2 R129.2 R131.2 R143.2 R145.2 U10.B2(VL) U10.B3(~{TS}) U17.B2(VL) U17.B3(~{TS}) U19.B2(VL) U19.B3(~{TS}) U66.B2(VL) U66.B3(~{TS}) ; also on sheet 6 9 15 16 17 19 20 24 30 31 39 45
2.5V: C827.1 C843.1 C844.1 J28.1 J28.3 L18.1 L21.2 R207.2 R279.2 R5287.1 U10.B1(VCC) ; also on sheet 18 19 21 23 31 32 43 46
2.5V_SDI: C217.1 C218.1 C219.1 C221.1 L21.1 R167.2 R168.2 U21.7(SDO1_DISABLE) U21.20(VCC) U21.24(VCC)
3.3V: C179.1 C180.1 C187.1 C188.1 C195.1 C196.1 C828.1 J13.C39(3P3V) J13.D32(3P3VAUX) J13.D36(3P3V) J13.D38(3P3V) J13.D40(3P3V) J28.7 J28.9 L10.1 L11.1 L12.1 L16.1 R112.1 R113.2 R114.2 R122.2 R124.2 R126.2 R128.2 R130.2 R142.2 R144.2 R457.2 R5355.2 U17.B1(VCC) U19.B1(VCC) ; also on sheet 9 17 18 19 23 24 30 32 34
12V: C829.1 J13.C35(12P0V) J13.C37(12P0V) J28.13 J28.15 ; also on sheet 32 33
GND: C175.1 C176.1 C179.2 C180.2 C181.2 C182.2 C183.2 C184.2 C185.2 C186.2 C187.2 C188.2 C189.2 C190.2 C194.2 C195.2 C196.2 C206.2 C207.2 C208.2 C209.2 C214.2 C215.2 C217.2 C218.2 C219.2 C221.2 C826.2 C827.2 C828.2 C829.2 C839.2 C840.2 C841.2 C842.2 C843.2 C844.2 C873.2 C874.2 J13.A1(GND) J13.A4(GND) J13.A5(GND) J13.A8(GND) J13.A9(GND) J13.A12(GND) J13.A13(GND) J13.A16(GND) J13.A17(GND) J13.A20(GND) J13.A21(GND) J13.A24(GND) J13.A25(GND) J13.A28(GND) J13.A29(GND) J13.A32(GND) J13.A33(GND) J13.A36(GND) J13.A37(GND) J13.A40(GND) J13.B2(GND) J13.B3(GND) J13.B6(GND) J13.B7(GND) J13.B10(GND) J13.B11(GND) J13.B14(GND) J13.B15(GND) J13.B18(GND) J13.B19(GND) J13.B22(GND) J13.B23(GND) J13.B26(GND) J13.B27(GND) J13.B30(GND) J13.B31(GND) J13.B34(GND) J13.B35(GND) J13.B38(GND) J13.B39(GND) J13.C1(GND) J13.C4(GND) J13.C5(GND) J13.C8(GND) J13.C9(GND) J13.C12(GND) J13.C13(GND) J13.C16(GND) J13.C17(GND) J13.C20(GND) J13.C21(GND) J13.C24(GND) J13.C25(GND) J13.C28(GND) J13.C29(GND) J13.C32(GND) J13.C33(GND) J13.C36(GND) J13.C38(GND) J13.C40(GND) J13.D2(GND) J13.D3(GND) J13.D6(GND) J13.D7(GND) J13.D10(GND) J13.D13(GND) J13.D16(GND) J13.D19(GND) J13.D22(GND) J13.D25(GND) J13.D28(GND) J13.D37(GND) J13.D39(GND) J13.E1(GND) J13.E4(GND) J13.E5(GND) J13.E8(GND) J13.E11(GND) J13.E14(GND) J13.E17(GND) J13.E20(GND) J13.E23(GND) J13.E26(GND) J13.E29(GND) J13.E32(GND) J13.E35(GND) J13.E38(GND) J13.E40(GND) J13.F2(GND) J13.F3(GND) J13.F6(GND) J13.F9(GND) J13.F12(GND) J13.F15(GND) J13.F18(GND) J13.F21(GND) J13.F24(GND) J13.F27(GND) J13.F30(GND) J13.F33(GND) J13.F36(GND) J13.F39(GND) J13.G1(GND) J13.G4(GND) J13.G5(GND) J13.G8(GND) J13.G11(GND) J13.G14(GND) J13.G17(GND) J13.G20(GND) J13.G23(GND) J13.G26(GND) J13.G29(GND) J13.G32(GND) J13.G35(GND) J13.G38(GND) J13.G40(GND) J13.H3(GND) J13.H6(GND) J13.H9(GND) J13.H12(GND) J13.H15(GND) J13.H18(GND) J13.H21(GND) J13.H24(GND) J13.H27(GND) J13.H30(GND) J13.H33(GND) J13.H36(GND) J13.H39(GND) J13.J1(GND) J13.J4(GND) J13.J5(GND) J13.J7(HA_N3) J13.J8(GND) J13.J10(HA_N7) J13.J11(GND) J13.J13(HA_N11) J13.J14(GND) J13.J16(HA_N14) J13.J17(GND) J13.J19(HA_N18) J13.J20(GND) J13.J22(HA_N22) J13.J23(GND) J13.J25(HB_N1) J13.J26(GND) J13.J28(HB_N7) J13.J29(GND) J13.J31(HB_N11) J13.J32(GND) J13.J34(HB_N15) J13.J35(GND) J13.J37(HB_N18) J13.J38(GND) J13.J40(GND) J13.K2(GND) J13.K3(GND) J13.K6(GND) J13.K9(GND) J13.K12(GND) J13.K15(GND) J13.K18(GND) J13.K21(GND) J13.K24(GND) J13.K27(GND) J13.K30(GND) J13.K33(GND) J13.K36(GND) J13.K39(GND) J15.1(GND) J15.4(GND) J15.7(GND) J15.13(GND) J15.16(GND) J15.19(GND) J15.20(GND) J15.23(GND) J15.26(GND) J15.32(GND) J15.35(GND) J15.38(GND) J17.2 J17.3 J17.4 J17.5 J18.2 J18.3 J18.4 J18.5 J28.5 J28.6 J28.11 J28.61 J28.62 J28.63 J28.64 R116.2 R146.1 R152.2 R154.2 R156.2 R160.2 R161.2 R162.1 R163.2 R169.2 R170.2 R210.1 R211.1 R5356.1 R5358.1 R5393.2 R5394.2 SW3.3(A3) SW4.2(A2) U10.B4(GND) U17.B4(GND) U19.B4(GND) U20.3(AVSS) U20.6(MUTE2) U20.8(AVSS) U20.15(AVSS) U20.17(CNTR_PAD) U21.1(VEE) U21.5(VEE) U21.12(VEE) U21.13(xCS) U21.16(VEE) U21.23(VEE) U21.25(VEE_PAD) U66.B4(GND) ; also on sheet 6 7 8 9 10 11 12 13 14 15 16 17 18 19 20 21 23 24 30 31 32 33 34 35 36 37 38 39 40 41 42 43 44 45 46
GND_QSFP_CAGE: C190.1 QSFP_CAGE1.1(Pin1) QSFP_CAGE1.2(Pin2) QSFP_CAGE1.3(Pin3) QSFP_CAGE1.4(Pin4) QSFP_CAGE1.5(Pin5) QSFP_CAGE1.6(Pin6) QSFP_CAGE1.7(Pin7) QSFP_CAGE1.8(Pin8) QSFP_CAGE1.9(Pin9) QSFP_CAGE1.10(Pin10) QSFP_CAGE1.11(Pin11) R146.2
AGCn: C224.2 U21.9(AGC-)
AGXp: C224.1 U21.8(AGC+)
BLASTER_DISn: J28.43 ; also on sheet 30
CLK0_OEn: R5393.1 SW3.8(B1) ; also on sheet 18 19
CLK0_RSTn: SW3.7(B2) ; also on sheet 18 19
CPU_RESETn: J28.27 ; also on sheet 10 19
EXT_JTAG_TCK: J28.51 ; also on sheet 30
EXT_JTAG_TDI: J28.49 ; also on sheet 30
EXT_JTAG_TDO: J28.45 ; also on sheet 30
EXT_JTAG_TMS: J28.47 ; also on sheet 30
FACTORY_LOAD: R207.1 SW3.6(B3) ; also on sheet 19
FMCA_3P3V_SCL: J13.C30(SCL) ; also on sheet 9
FMCA_3P3V_SDA: J13.C31(SDA) ; also on sheet 9
FMCA_C2M_3p3V_PWRGD: J13.D1(PG_C2M) R112.2 ; also on sheet 30
FMCA_CLK_M2C_N0: J13.H5(CLK0_M2C_N) ; also on sheet 9
FMCA_CLK_M2C_N1: J13.G3(CLK1_M2C_N) ; also on sheet 9
FMCA_CLK_M2C_P0: J13.H4(CLK0_M2C_P) ; also on sheet 9
FMCA_CLK_M2C_P1: J13.G2(CLK1_M2C_P) ; also on sheet 9
FMCA_DP_C2M_N0: J13.C3(DP0_C2M_N) ; also on sheet 13
FMCA_DP_C2M_N1: J13.A23(DP1_C2M_N) ; also on sheet 13
FMCA_DP_C2M_N2: J13.A27(DP2_C2M_N) ; also on sheet 13
FMCA_DP_C2M_N3: J13.A31(DP3_C2M_N) ; also on sheet 13
FMCA_DP_C2M_N4: J13.A35(DP4_C2M_N) ; also on sheet 13
FMCA_DP_C2M_N5: J13.A39(DP5_C2M_N) ; also on sheet 13
FMCA_DP_C2M_N6: J13.B37(DP6_C2M_N) ; also on sheet 13
FMCA_DP_C2M_N7: J13.B33(DP7_C2M_N) ; also on sheet 13
FMCA_DP_C2M_N8: J13.B29(DP8_C2M_N) ; also on sheet 13
FMCA_DP_C2M_N9: J13.B25(DP9_C2M_N) ; also on sheet 13
FMCA_DP_C2M_N10: J13.K23(HA_N23) ; also on sheet 13
FMCA_DP_C2M_N11: J13.K26(HB_N0_CC) ; also on sheet 13
FMCA_DP_C2M_N12: J13.K29(HB_N6_CC) ; also on sheet 13
FMCA_DP_C2M_N13: J13.K32(HB_N10) ; also on sheet 13
FMCA_DP_C2M_N14: J13.K35(HB_N14) ; also on sheet 13
FMCA_DP_C2M_N15: J13.K38(HB_N17_CC) ; also on sheet 13
FMCA_DP_C2M_P0: J13.C2(DP0_C2M_P) ; also on sheet 13
FMCA_DP_C2M_P1: J13.A22(DP1_C2M_P) ; also on sheet 13
FMCA_DP_C2M_P2: J13.A26(DP2_C2M_P) ; also on sheet 13
FMCA_DP_C2M_P3: J13.A30(DP3_C2M_P) ; also on sheet 13
FMCA_DP_C2M_P4: J13.A34(DP4_C2M_P) ; also on sheet 13
FMCA_DP_C2M_P5: J13.A38(DP5_C2M_P) ; also on sheet 13
FMCA_DP_C2M_P6: J13.B36(DP6_C2M_P) ; also on sheet 13
FMCA_DP_C2M_P7: J13.B32(DP7_C2M_P) ; also on sheet 13
FMCA_DP_C2M_P8: J13.B28(DP8_C2M_P) ; also on sheet 13
FMCA_DP_C2M_P9: J13.B24(DP9_C2M_P) ; also on sheet 13
FMCA_DP_C2M_P10: J13.K22(HA_P23) ; also on sheet 13
FMCA_DP_C2M_P11: J13.K25(HB_P0_CC) ; also on sheet 13
FMCA_DP_C2M_P12: J13.K28(HB_P6_CC) ; also on sheet 13
FMCA_DP_C2M_P13: J13.K31(HB_P10) ; also on sheet 13
FMCA_DP_C2M_P14: J13.K34(HB_P14) ; also on sheet 13
FMCA_DP_C2M_P15: J13.K37(HB_P17_CC) ; also on sheet 13
FMCA_DP_M2C_N0: J13.C7(DP0_M2C_N) ; also on sheet 13
FMCA_DP_M2C_N1: J13.A3(DP1_M2C_N) ; also on sheet 13
FMCA_DP_M2C_N2: J13.A7(DP2_M2C_N) ; also on sheet 13
FMCA_DP_M2C_N3: J13.A11(DP3_M2C_N) ; also on sheet 13
FMCA_DP_M2C_N4: J13.A15(DP4_M2C_N) ; also on sheet 13
FMCA_DP_M2C_N5: J13.A19(DP5_M2C_N) ; also on sheet 13
FMCA_DP_M2C_N6: J13.B17(DP6_M2C_N) ; also on sheet 13
FMCA_DP_M2C_N7: J13.B13(DP7_M2C_N) ; also on sheet 13
FMCA_DP_M2C_N8: J13.B9(DP8_M2C_N) ; also on sheet 13
FMCA_DP_M2C_N9: J13.B5(DP9_M2C_N) ; also on sheet 13
FMCA_DP_M2C_N10: J13.K5(CLK2_BIDIR_N) ; also on sheet 13
FMCA_DP_M2C_N11: J13.K8(HA_N2) ; also on sheet 13
FMCA_DP_M2C_N12: J13.K11(HA_N6) ; also on sheet 13
FMCA_DP_M2C_N13: J13.K14(HA_N10) ; also on sheet 13
FMCA_DP_M2C_N14: J13.K17(HA_N17_CC) ; also on sheet 13
FMCA_DP_M2C_N15: J13.K20(HA_N21) ; also on sheet 13
FMCA_DP_M2C_P0: J13.C6(DP0_M2C_P) ; also on sheet 13
FMCA_DP_M2C_P1: J13.A2(DP1_M2C_P) ; also on sheet 13
FMCA_DP_M2C_P2: J13.A6(DP2_M2C_P) ; also on sheet 13
FMCA_DP_M2C_P3: J13.A10(DP3_M2C_P) ; also on sheet 13
FMCA_DP_M2C_P4: J13.A14(DP4_M2C_P) ; also on sheet 13
FMCA_DP_M2C_P5: J13.A18(DP5_M2C_P) ; also on sheet 13
FMCA_DP_M2C_P6: J13.B16(DP6_M2C_P) ; also on sheet 13
FMCA_DP_M2C_P7: J13.B12(DP7_M2C_P) ; also on sheet 13
FMCA_DP_M2C_P8: J13.B8(DP8_M2C_P) ; also on sheet 13
FMCA_DP_M2C_P9: J13.B4(DP9_M2C_P) ; also on sheet 13
FMCA_DP_M2C_P10: J13.K4(CLK2_BIDIR_P) ; also on sheet 13
FMCA_DP_M2C_P11: J13.K7(HA_P2) ; also on sheet 13
FMCA_DP_M2C_P12: J13.K10(HA_P6) ; also on sheet 13
FMCA_DP_M2C_P13: J13.K13(HA_P10) ; also on sheet 13
FMCA_DP_M2C_P14: J13.K16(HA_P17_CC) ; also on sheet 13
FMCA_DP_M2C_P15: J13.K19(HA_P21) ; also on sheet 13
FMCA_GA0: J13.C34(GA0) R457.1 R5358.2 ; also on sheet 9
FMCA_GA1: J13.D35(GA1) R5355.1 R5356.2 ; also on sheet 9
FMCA_GBTCLK_M2C_N0: J13.D5(GBTCLK0_M2C_N) ; also on sheet 13
FMCA_GBTCLK_M2C_N1: J13.B21(GBTCLK1_M2C_N) ; also on sheet 13
FMCA_GBTCLK_M2C_P0: J13.D4(GBTCLK0_M2C_P) ; also on sheet 13
FMCA_GBTCLK_M2C_P1: J13.B20(GBTCLK1_M2C_P) ; also on sheet 13
FMCA_JTAG_RST: J13.D34(TRST) R114.1
FMCA_JTAG_TCK: J13.D29(TCK) ; also on sheet 30
FMCA_JTAG_TDI: J13.D30(TDI) ; also on sheet 30
FMCA_JTAG_TDO: J13.D31(TDO) ; also on sheet 30
FMCA_JTAG_TMS: J13.D33(TMS) ; also on sheet 30
FMCA_LA_RX_CLK_N0: J13.G7(LA_N0_CC) ; also on sheet 9
FMCA_LA_RX_CLK_N1: J13.D9(LA_N1_CC) ; also on sheet 9
FMCA_LA_RX_CLK_P0: J13.G6(LA_P0_CC) ; also on sheet 9
FMCA_LA_RX_CLK_P1: J13.D8(LA_P1_CC) ; also on sheet 9
FMCA_LA_RX_N0: J13.G10(LA_N3) ; also on sheet 9
FMCA_LA_RX_N1: J13.C11(LA_N6) ; also on sheet 9
FMCA_LA_RX_N2: J13.G13(LA_N8) ; also on sheet 9
FMCA_LA_RX_N3: J13.C15(LA_N10) ; also on sheet 9
FMCA_LA_RX_N4: J13.G16(LA_N12) ; also on sheet 9
FMCA_LA_RX_N5: J13.C19(LA_N14) ; also on sheet 9
FMCA_LA_RX_N6: J13.G19(LA_N16) ; also on sheet 9
FMCA_LA_RX_N7: J13.C23(LA_N18_CC) ; also on sheet 9
FMCA_LA_RX_N8: J13.G22(LA_N20) ; also on sheet 9
FMCA_LA_RX_N9: J13.G25(LA_N22) ; also on sheet 9
FMCA_LA_RX_N10: J13.G28(LA_N25) ; also on sheet 9
FMCA_LA_RX_N11: J13.C27(LA_N27) ; also on sheet 9
FMCA_LA_RX_N12: J13.G31(LA_N29) ; also on sheet 9
FMCA_LA_RX_N13: J13.G34(LA_N31) ; also on sheet 9
FMCA_LA_RX_N14: J13.G37(LA_N33) ; also on sheet 9
FMCA_LA_RX_P0: J13.G9(LA_P3) ; also on sheet 9
FMCA_LA_RX_P1: J13.C10(LA_P6) ; also on sheet 9
FMCA_LA_RX_P2: J13.G12(LA_P8) ; also on sheet 9
FMCA_LA_RX_P3: J13.C14(LA_P10) ; also on sheet 9
FMCA_LA_RX_P4: J13.G15(LA_P12) ; also on sheet 9
FMCA_LA_RX_P5: J13.C18(LA_P14) ; also on sheet 9
FMCA_LA_RX_P6: J13.G18(LA_P16) ; also on sheet 9
FMCA_LA_RX_P7: J13.C22(LA_P18_CC) ; also on sheet 9
FMCA_LA_RX_P8: J13.G21(LA_P20) ; also on sheet 9
FMCA_LA_RX_P9: J13.G24(LA_P22) ; also on sheet 9
FMCA_LA_RX_P10: J13.G27(LA_P25) ; also on sheet 9
FMCA_LA_RX_P11: J13.C26(LA_P27) ; also on sheet 9
FMCA_LA_RX_P12: J13.G30(LA_P29) ; also on sheet 9
FMCA_LA_RX_P13: J13.G33(LA_P31) ; also on sheet 9
FMCA_LA_RX_P14: J13.G36(LA_P33) ; also on sheet 9
FMCA_LA_TX_N0: J13.H8(LA_N2) ; also on sheet 9
FMCA_LA_TX_N1: J13.H11(LA_N4) ; also on sheet 9
FMCA_LA_TX_N2: J13.D12(LA_N5) ; also on sheet 9
FMCA_LA_TX_N3: J13.H14(LA_N7) ; also on sheet 9
FMCA_LA_TX_N4: J13.D15(LA_N9) ; also on sheet 9
FMCA_LA_TX_N5: J13.H17(LA_N11) ; also on sheet 9
FMCA_LA_TX_N6: J13.D18(LA_N13) ; also on sheet 9
FMCA_LA_TX_N7: J13.H20(LA_N15) ; also on sheet 9
FMCA_LA_TX_N8: J13.D21(LA_N17) ; also on sheet 9
FMCA_LA_TX_N9: J13.H23(LA_N19) ; also on sheet 9
FMCA_LA_TX_N10: J13.H26(LA_N21) ; also on sheet 9
FMCA_LA_TX_N11: J13.D24(LA_N23) ; also on sheet 9
FMCA_LA_TX_N12: J13.H29(LA_N24) ; also on sheet 9
FMCA_LA_TX_N13: J13.D27(LA_N26) ; also on sheet 9
FMCA_LA_TX_N14: J13.H32(LA_N28) ; also on sheet 9
FMCA_LA_TX_N15: J13.H35(LA_N30) ; also on sheet 9
FMCA_LA_TX_N16: J13.H38(LA_N32) ; also on sheet 9
FMCA_LA_TX_P0: J13.H7(LA_P2) ; also on sheet 9
FMCA_LA_TX_P1: J13.H10(LA_P4) ; also on sheet 9
FMCA_LA_TX_P2: J13.D11(LA_P5) ; also on sheet 9
FMCA_LA_TX_P3: J13.H13(LA_P7) ; also on sheet 9
FMCA_LA_TX_P4: J13.D14(LA_P9) ; also on sheet 9
FMCA_LA_TX_P5: J13.H16(LA_P11) ; also on sheet 9
FMCA_LA_TX_P6: J13.D17(LA_P13) ; also on sheet 9
FMCA_LA_TX_P7: J13.H19(LA_P15) ; also on sheet 9
FMCA_LA_TX_P8: J13.D20(LA_P17) ; also on sheet 9
FMCA_LA_TX_P9: J13.H22(LA_P19) ; also on sheet 9
FMCA_LA_TX_P10: J13.H25(LA_P21) ; also on sheet 9
FMCA_LA_TX_P11: J13.D23(LA_P23) ; also on sheet 9
FMCA_LA_TX_P12: J13.H28(LA_P24) ; also on sheet 9
FMCA_LA_TX_P13: J13.D26(LA_P26) ; also on sheet 9
FMCA_LA_TX_P14: J13.H31(LA_P28) ; also on sheet 9
FMCA_LA_TX_P15: J13.H34(LA_P30) ; also on sheet 9
FMCA_LA_TX_P16: J13.H37(LA_P32) ; also on sheet 9
FMCA_M2C_PWRGD: J13.F1(PG_M2C) R113.1
FMCA_PRSNTn: J13.H2(PRSNT_M2C_L) J28.18 ; also on sheet 10 19 30
FMCA_RX_LED: J28.14 ; also on sheet 10
FMCA_TX_LED: J28.16 ; also on sheet 10
I2C_SCL: J28.17 ; also on sheet 18 19 31 32
I2C_SDA: J28.19 ; also on sheet 18 19 31 32
JTAG_RX: J28.54 ; also on sheet 30
JTAG_TX: J28.56 ; also on sheet 30
MAX_CONF_DONE: J28.12 ; also on sheet 19
MAX_ERROR: J28.8 ; also on sheet 19
MAX_LOAD: J28.10 ; also on sheet 19
MAX_RESETn: J28.25 ; also on sheet 19
MF0_BYPASS: U10.C1(IO_VCC1) U21.10(MF0)
MF1_AUTO_SLEEP: U10.C2(IO_VCC2) U21.19(MF1)
MF2_MUTE: U10.C3(IO_VCC3) U21.21(MF2)
MF3_xSD: D9.C(CATHODE) R166.2 U21.22(MF3)
MODE_SEL: R163.1 U21.6(MODE_SEL)
MUTEREF: R162.2 R166.1 U21.11(MUTEREF)
PCIE_LED_G2: J28.50 ; also on sheet 10
PCIE_LED_G3: J28.52 ; also on sheet 10
PCIE_LED_X1: J28.42 ; also on sheet 10
PCIE_LED_X4: J28.44 ; also on sheet 10
PCIE_LED_X8: J28.46 ; also on sheet 10
PCIE_LED_X16: J28.48 ; also on sheet 10
PGM_CONFIG: J28.21 ; also on sheet 19
PGM_LED0: J28.36 ; also on sheet 19
PGM_LED1: J28.38 ; also on sheet 19
PGM_LED2: J28.40 ; also on sheet 19
PGM_SEL: J28.23 ; also on sheet 19
QSFP1_3p3V_INTERRUPTn: J15.28(Intl) R128.1 U17.C3(IO_VCC3)
QSFP1_3p3V_LP_MODE: J15.31(LPMode) R126.1 U17.C2(IO_VCC2)
QSFP1_3p3V_MOD_PRSn: J15.27(ModPrsL) R130.1 U17.C4(IO_VCC4)
QSFP1_3p3V_MOD_SELn: J15.8(ModselL) R122.1 U19.C1(IO_VCC1)
QSFP1_3p3V_RSTn: J15.9(ResetL) R124.1 U17.C1(IO_VCC1)
QSFP1_INTERRUPTn: R129.1 U17.A3(IO_VL3) ; also on sheet 8
QSFP1_LP_MODE: R127.1 U17.A2(IO_VL2) ; also on sheet 8
QSFP1_MOD_PRSn: R131.1 U17.A4(IO_VL4) ; also on sheet 8
QSFP1_MOD_SELn: R123.1 U19.A1(IO_VL1) ; also on sheet 8
QSFP1_RSTn: R125.1 U17.A1(IO_VL1) ; also on sheet 8
QSFP1_RX_N0: J15.18(RX1n) ; also on sheet 12
QSFP1_RX_N1: J15.21(RX2n) ; also on sheet 12
QSFP1_RX_N2: J15.15(RX3n) ; also on sheet 12
QSFP1_RX_N3: J15.24(RX4n) ; also on sheet 12
QSFP1_RX_P0: J15.17(RX1p) ; also on sheet 12
QSFP1_RX_P1: J15.22(RX2p) ; also on sheet 12
QSFP1_RX_P2: J15.14(RX3p) ; also on sheet 12
QSFP1_RX_P3: J15.25(RX4p) ; also on sheet 12
QSFP1_TX_N0: J15.37(TX1n) ; also on sheet 12
QSFP1_TX_N1: J15.2(TX2n) ; also on sheet 12
QSFP1_TX_N2: J15.34(TX3n) ; also on sheet 12
QSFP1_TX_N3: J15.5(TX4n) ; also on sheet 12
QSFP1_TX_P0: J15.36(TX1p) ; also on sheet 12
QSFP1_TX_P1: J15.3(TX2p) ; also on sheet 12
QSFP1_TX_P2: J15.33(TX3p) ; also on sheet 12
QSFP1_TX_P3: J15.6(TX4p) ; also on sheet 12
QSFP1_VCC: C185.1 C186.1 J15.30(VCC1) L12.2
QSFP1_VCCR: C183.1 C184.1 J15.10(VCCRX) L11.2
QSFP1_VCCT: C181.1 C182.1 J15.29(VCCTX) L10.2
QSFP_3p3V_SCL: J15.11(SCL) R142.1 U19.C3(IO_VCC3)
QSFP_3p3V_SDA: J15.12(SDA) R144.1 U19.C4(IO_VCC4)
QSFP_SCL: R143.1 U19.A3(IO_VL3) ; also on sheet 8
QSFP_SDA: R145.1 U19.A4(IO_VL4) ; also on sheet 8
RZQ_B2M: R210.2 SW4.8(B1) ; also on sheet 8
S10_SI516_FS: U10.A4(IO_VL4) ; also on sheet 10
S10_VCCIO_FMCA: J13.E39(VADJ) J13.F40(VADJ) J13.G39(VADJ) J13.H40(VADJ) J13.J39(VIO_B_M2C) J13.K40(VIO_B_M2C) R115.1 ; also on sheet 9 15 31 41 45
SC_RX: J28.58 ; also on sheet 30
SC_TX: J28.60 ; also on sheet 30
SDI_AVDD: C206.1 C207.1 C208.1 C209.1 C839.1 C840.1 L16.2 L18.2 R149.2 R150.2 R151.2 R153.2 U20.2(AVDD) U20.7(AVDD) U20.14(MUTE1) U66.B1(VCC)
SDI_EQIN_N: C220.1 R161.1
SDI_EQIN_N1: C220.2 U21.4(SDIN)
SDI_EQIN_P: C216.1 L20.2 R159.1 R160.1
SDI_EQIN_P1: C216.2 U21.3(SDIP)
SDI_IN_P1: J18.1 L20.1 R159.2
SDI_MF0_BYPASS: R169.1 U10.A1(IO_VL1) ; also on sheet 7 19
SDI_MF1_AUTO_SLEEP: R168.1 U10.A2(IO_VL2) ; also on sheet 7 19
SDI_MF2_MUTE: R170.1 U10.A3(IO_VL3) ; also on sheet 7 19
SDI_RX_N: C223.2 ; also on sheet 12
SDI_RX_P: C222.2 ; also on sheet 12
SDI_SD_HDn: U20.9(SD/XHD) U66.C1(IO_VCC1)
SDI_TX: C214.1 C215.1 R157.1 R158.1
SDI_TX_N: C212.1 ; also on sheet 12
SDI_TX_P: C211.1 ; also on sheet 12
SDI_TX_RSET: R153.1 R154.1 U20.5(RSET)
SDI_TX_SD_HDn: U66.A1(IO_VL1) ; also on sheet 7 19
SDI_TXBNC: C210.1 L17.2 R148.2
SDI_TXBNC_P: C210.2 J17.1
SDI_TXCAP_N: C212.2 R157.2 U20.1(SDIN)
SDI_TXCAP_P: C211.2 R158.2 U20.16(SDIP)
SDI_TXDRV_N: L19.1 R151.1 R155.1 U20.10(SDO2N)
SDI_TXDRV_P: L17.1 R148.1 R149.1 U20.11(SDO2P)
SDI_TXDRV_TERM: C213.1 L19.2 R155.2
SDO_N: C223.1 U21.14(SDO0N)
SDO_P: C222.1 U21.15(SDO0P)
SI516_FS: R279.1 SW4.7(B2) U10.C4(IO_VCC4) ; also on sheet 18 19
USB_MAX_TCK: J28.59 ; also on sheet 30
USB_MAX_TDI: J28.57 ; also on sheet 30
USB_MAX_TDO: J28.53 ; also on sheet 30
USB_MAX_TMS: J28.55 ; also on sheet 30
USER_DIPSW0: J28.35 ; also on sheet 10
USER_DIPSW1: J28.37 ; also on sheet 10
USER_DIPSW2: J28.39 ; also on sheet 10
USER_DIPSW3: J28.41 ; also on sheet 10
USER_LED_G0: J28.20 ; also on sheet 10
USER_LED_G1: J28.24 ; also on sheet 10
USER_LED_G2: J28.28 ; also on sheet 10
USER_LED_G3: J28.32 ; also on sheet 10
USER_LED_R0: J28.22 ; also on sheet 10
USER_LED_R1: J28.26 ; also on sheet 10
USER_LED_R2: J28.30 ; also on sheet 10
USER_LED_R3: J28.34 ; also on sheet 10
USER_PB0: J28.29 ; also on sheet 10
USER_PB1: J28.31 ; also on sheet 10
USER_PB2: J28.33 ; also on sheet 10
VREF_FMCA: C175.2 C176.2 J13.H1(VREF_A_M2C) R115.2 R116.1 ; also on sheet 15 45
N17025782: D9.A(ANODE) R167.1
N17025943: R150.1 R152.1 U20.4(NC)
N17026009: C873.1 C874.1 U21.2(VEE)
N17026686: C213.2 R156.1
N20476833: R211.2 SW4.1(A1)
N21418828: R5287.2 SW3.1(A1)
N22608584: R5394.1 SW3.2(A2)

Not connected (* = marked no-connect by the designer): J13 B1(CLK_DIR)* B40(RES0)* E2(HA_P1_CC)* E3(HA_N1_CC)* E6(HA_P5)* E7(HA_N5)* E9(HA_P9)* E10(HA_N9)* E12(HA_P13)* E13(HA_N13)* E15(HA_P16)* E16(HA_N16)* E18(HA_P20)* E19(HA_N20)* E21(HB_P3)* E22(HB_N3)* E24(HB_P5)* E25(HB_N5)* E27(HB_P9)* E28(HB_N9)* E30(HB_P13)* E31(HB_N13)* E33(HB_P19)* E34(HB_N19)* E36(HB_P21)* E37(HB_N21)* F4(HA_P0_CC)* F5(HA_N0_CC)* F7(HA_P4)* F8(HA_N4)* F10(HA_P8)* F11(HA_N8)* F13(HA_P12)* F14(HA_N12)* F16(HA_P15)* F17(HA_N15)* F19(HA_P19)* F20(HA_N19)* F22(HB_P2)* F23(HB_N2)* F25(HB_P4)* F26(HB_N4)* F28(HB_P8)* F29(HB_N8)* F31(HB_P12)* F32(HB_N12)* F34(HB_P16)* F35(HB_N16)* F37(HB_P20)* F38(HB_N20)* J2(CLK3_BIDIR_P)* J3(CLK3_BIDIR_N)* J6(HA_P3)* J9(HA_P7)* J12(HA_P11)* J15(HA_P14)* J18(HA_P18)* J21(HA_P22)* J24(HB_P1)* J27(HB_P7)* J30(HB_P11)* J33(HB_P15)* J36(HB_P18)* K1(VREF_B_M2C)*; J15 39(MTH1)* 40(MTH2)*; SW3 4(A4)* 5(B4)*; SW4 3(A3)* 4(A4)* 5(B4)* 6(B3)*; U19 A2(IO_VL2)* C2(IO_VCC2)*; U20 12(SDO1N)* 13(SDO1P)*; U21 17(SDO1N)* 18(SDO1P)*; U66 A2(IO_VL2)* A3(IO_VL3)* A4(IO_VL4)* C2(IO_VCC2)* C3(IO_VCC3)* C4(IO_VCC4)*

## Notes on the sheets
sheet 25
- FMC Port A
- LVDS P/N NEED TO BE MATCHED BY +/-10ps WITH COMPENSATION ON BOARD FOR PACKAGE DELAYS.
- FMCA INTERFACE
- A10_VCCIO_FMCA
  limited to 1.8V
- PG_M2C only on High
  Pincount versions.
- CLK2_BIDIR,  CLK3_BIDIR,
  and CLK_DIR only on High
  Pincount versions.
sheet 26
- This page intentionally left blank
sheet 27
- QSFP
- Quad Small Form-factor Pluggable (QSFP) Interface
- NOTE 1: Bypass Capacitors should be placed as close to the associated 20-pin
  connector as possible.
- QSFP1
- NOTE 2: Assuming that the SFP RD 100-ohm termination on the Host Board FPGA
  device will be implemented via the on-chip termination circuit.
- NOTE 3: DC blocking capacitors are in the module for RX and TX.
- NOTE 4: 1uH inductors should have a DC Resistance of less than 0.1-ohm.
- QSFP1 INTERFACE
- Maximum power is <= 3.5W  (1.06 A)
  Maximum inrush current = 1.3A
- I2C Address = A0h
- H = 0.33mm
  Place on Bottom side
- H = 0.33mm
  Place on Bottom side
sheet 28
- 12G SDI
- NEW CHIPSET AVAILABLE - CHECK WITH MACOM
- SDI Transmit
- 75 Ohm Single-Ended Impedance
- M22468 Pin compatible to:
  M22428 (Gen2 3G/6G SDI Cable Driver)
  M23428 (12G Cable Driver)
- 100 Ohm Differential Impedance
- DNI 75-ohm  to SDI_AVDD
  resitors for 12G.
- Pin 4 -> GEN2 EQ Control:
  Float = no input EQ
  Low = 2dB EQ
  High = 4dB EQ
- Pull-down for 12G
- Layout Notes:
  DNI for resistors and
  capacitors for GEN2
  devices.
  Minimize stubs in
  layout.
- Layout Notes (M22468) SDI Cable Driver:
  - The RSET resistor should be located close to pin 5.
  - Remove GND under pin 5 and the RSET resistor.
  - The 49.9-ohm resistors should be placed close to device pins 16 and 1 (SDIP/SDIN).
- SDI Receive
- 75 Ohm Single-Ended Impedance
- M22544 Pin Compatible to:
  M23544 (12G EQ + Reclocker)
- DISABLE SDO1 ->
- 100 Ohm Differential Impedance
- MODE_SEL = 0 -> HARDWARE MODE
- Layout Notes (M22544) SDI Cable Equalizer:
  - The AGC 33nF capacitor should be located close to the device pins 8 and 9 (AGC+/AGC-).
  - Clear GND under the AGC 33nF capacitor.
sheet 29
- LCD, User PB, SW, I/Os
- PUSH BUTTON INTERFACE
- LED INTERFACE
- DIPSWITCH INTERFACE
- QDRIV needs 1.3V VDD.
  SW7.4 allows changing of
  1.35V to 1.3V for QDRIV.
